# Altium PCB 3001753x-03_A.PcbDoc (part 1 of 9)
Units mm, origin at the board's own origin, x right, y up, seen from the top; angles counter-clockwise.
Board outline 210 x 130 mm, 8 copper layers (1-TOP, 2-GND, 3-INTOP, 4-PWR, 5-PWR, 6-INBOT, 7-GND, 8-BOTTOM), stack 1.646 mm thick; 676 components, 623 nets, 2861 pads, 2382 vias.
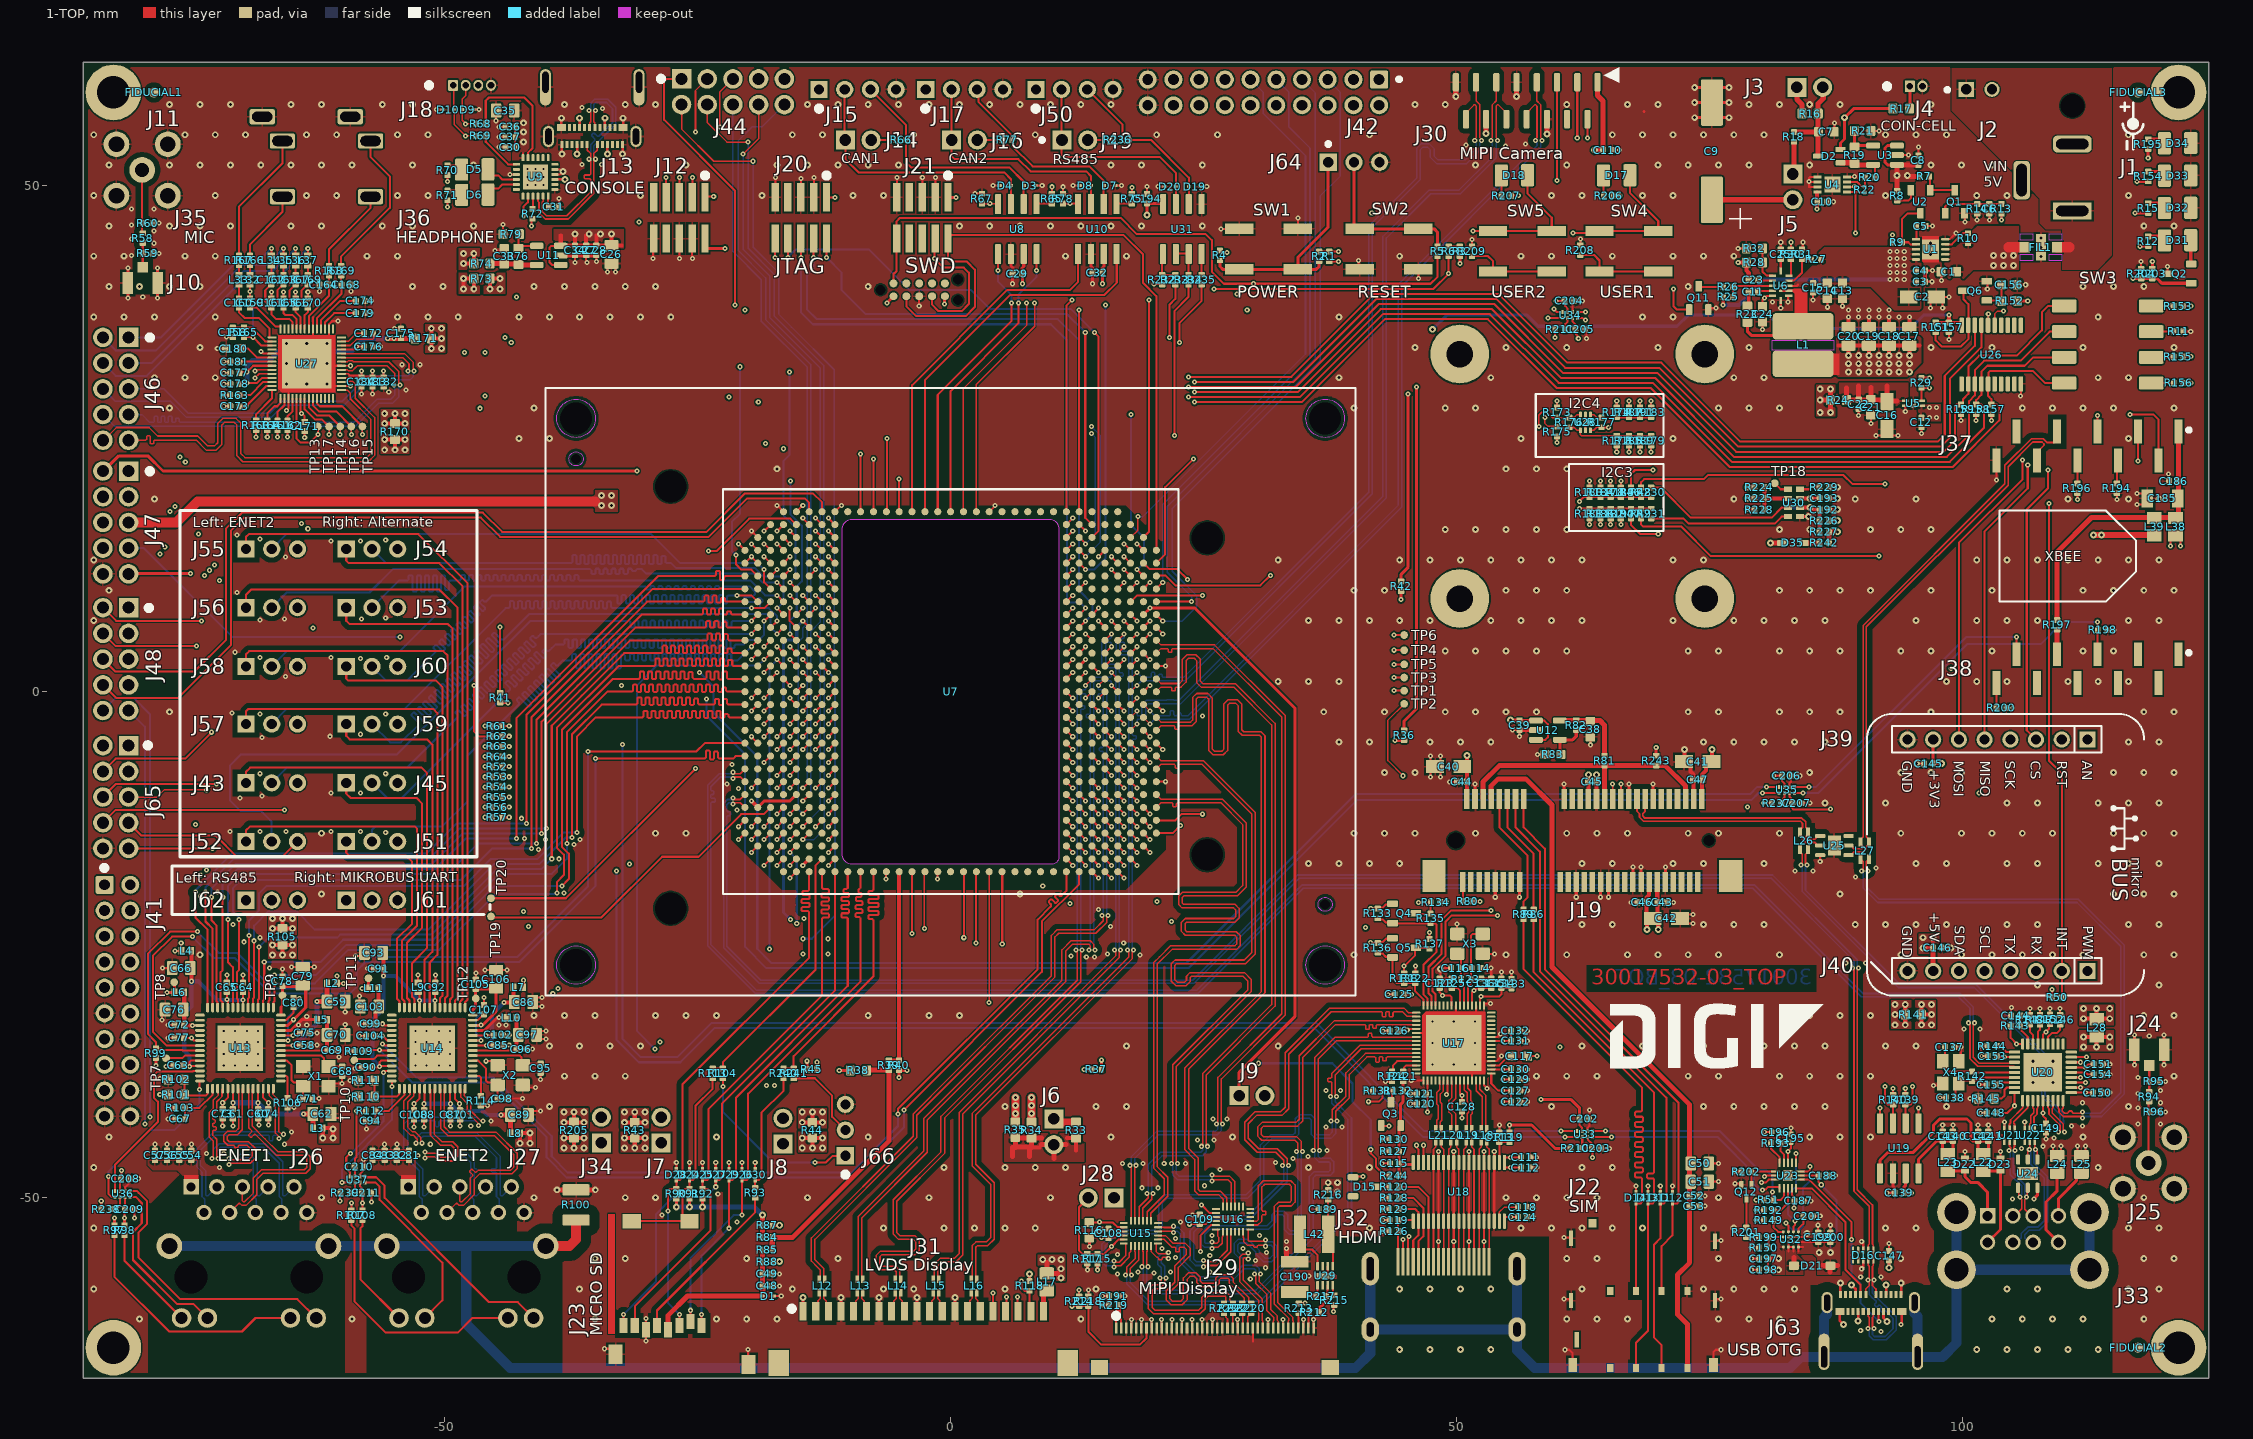
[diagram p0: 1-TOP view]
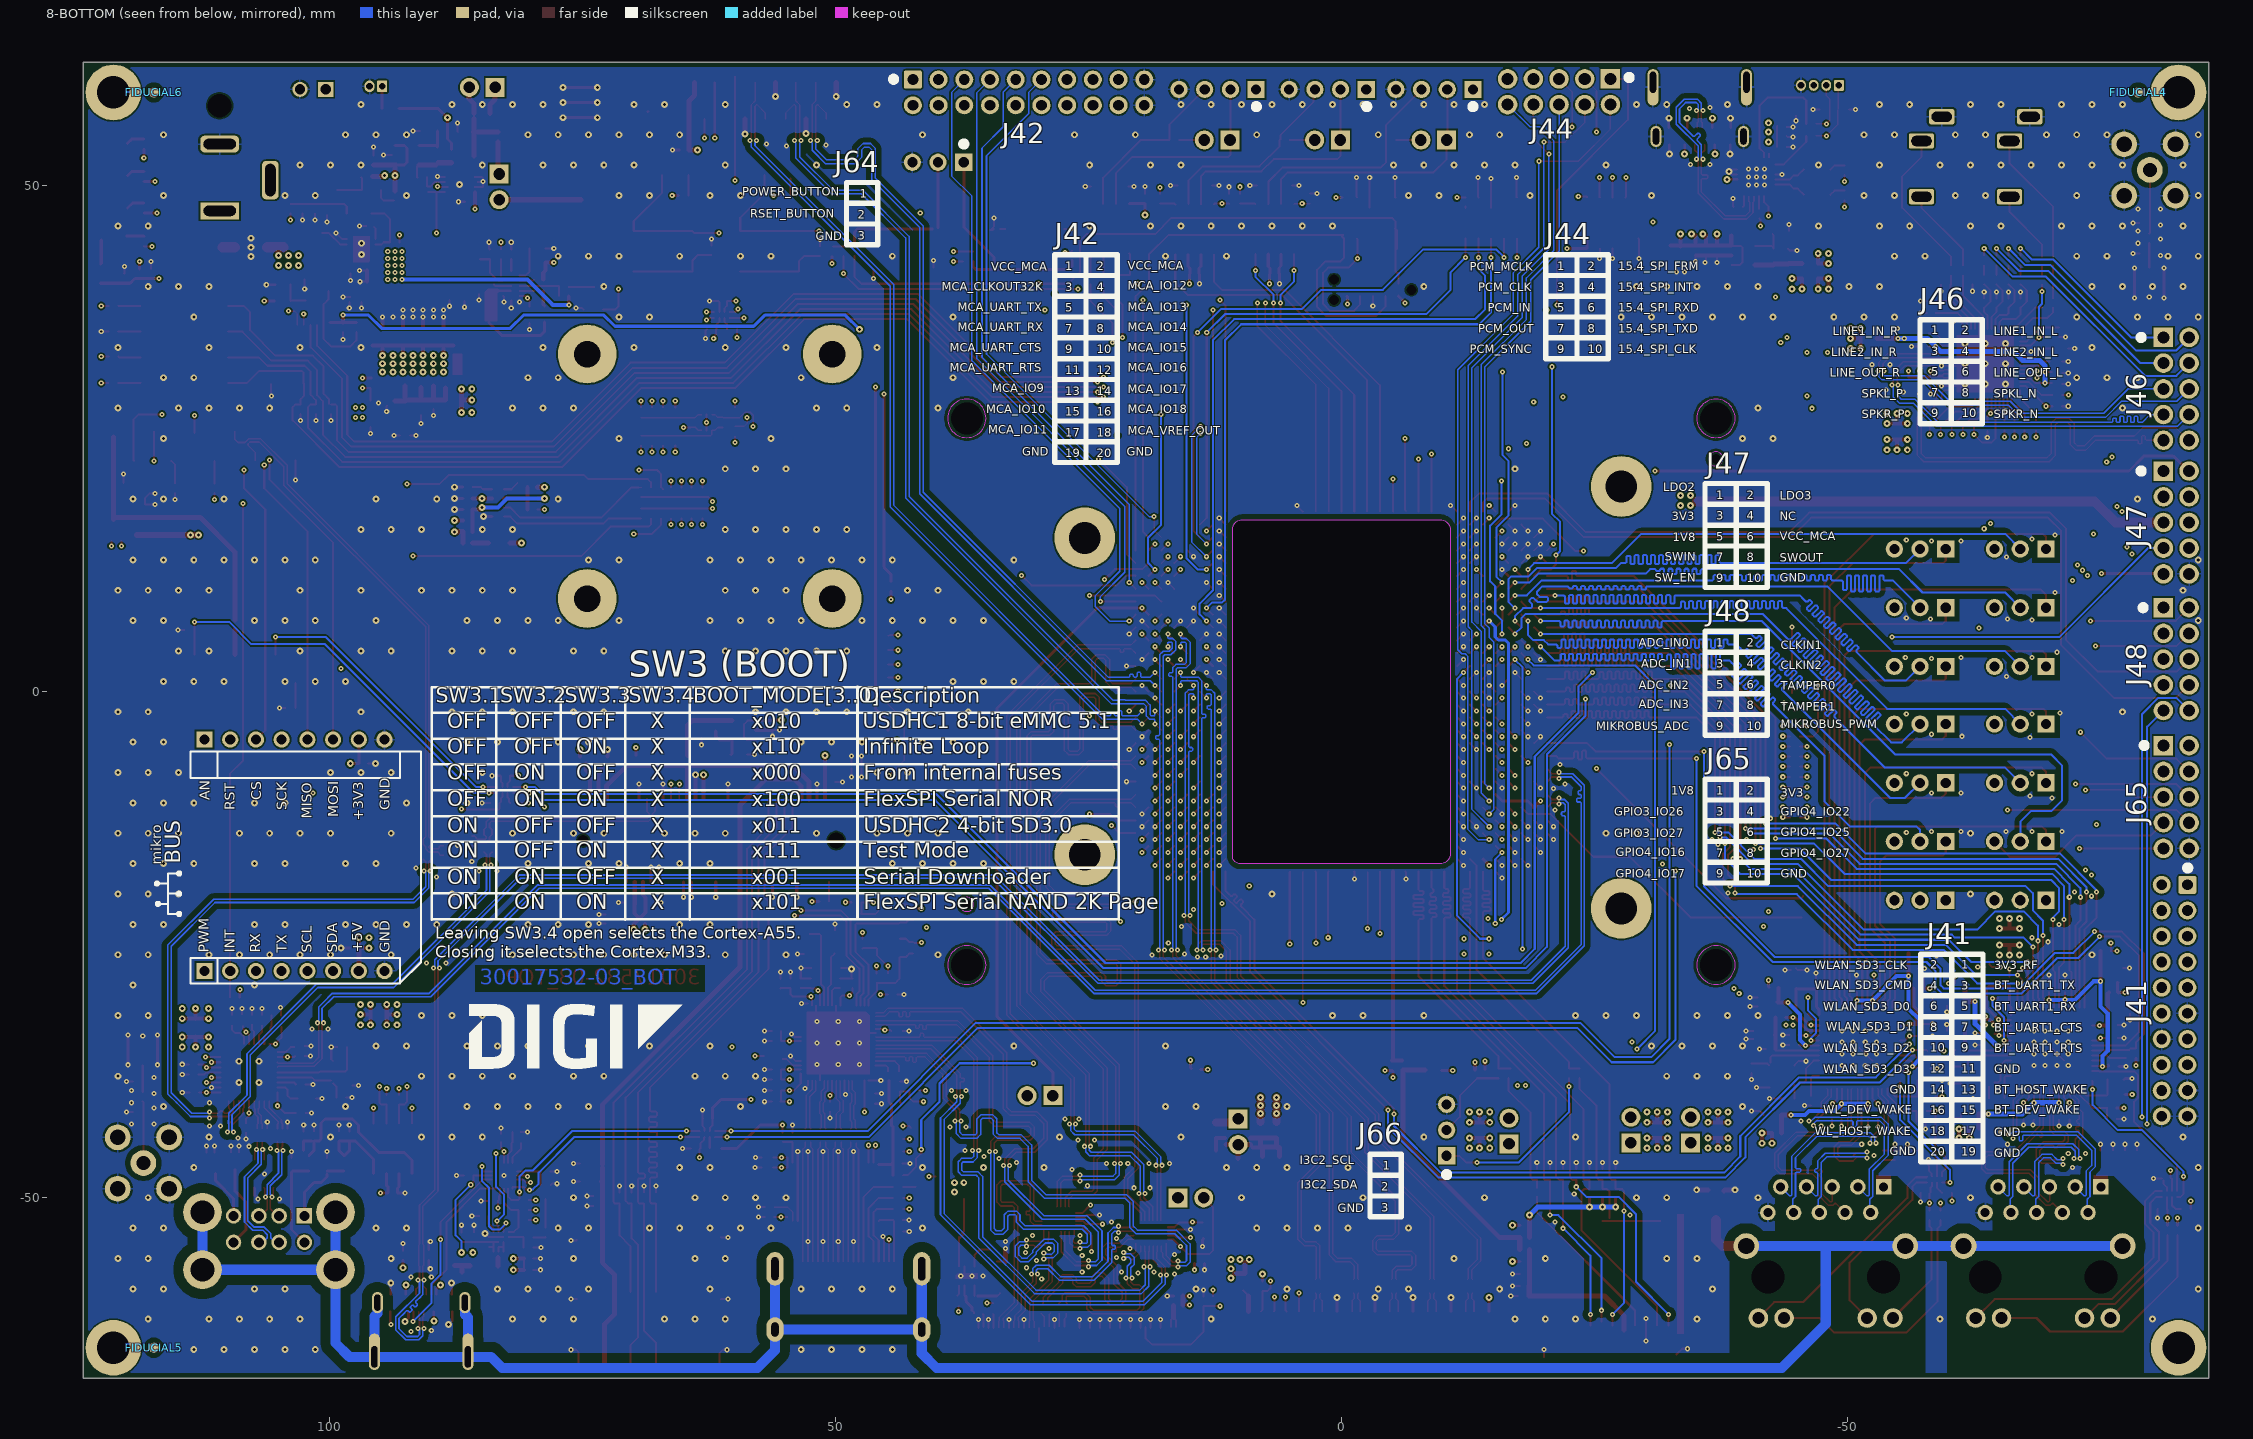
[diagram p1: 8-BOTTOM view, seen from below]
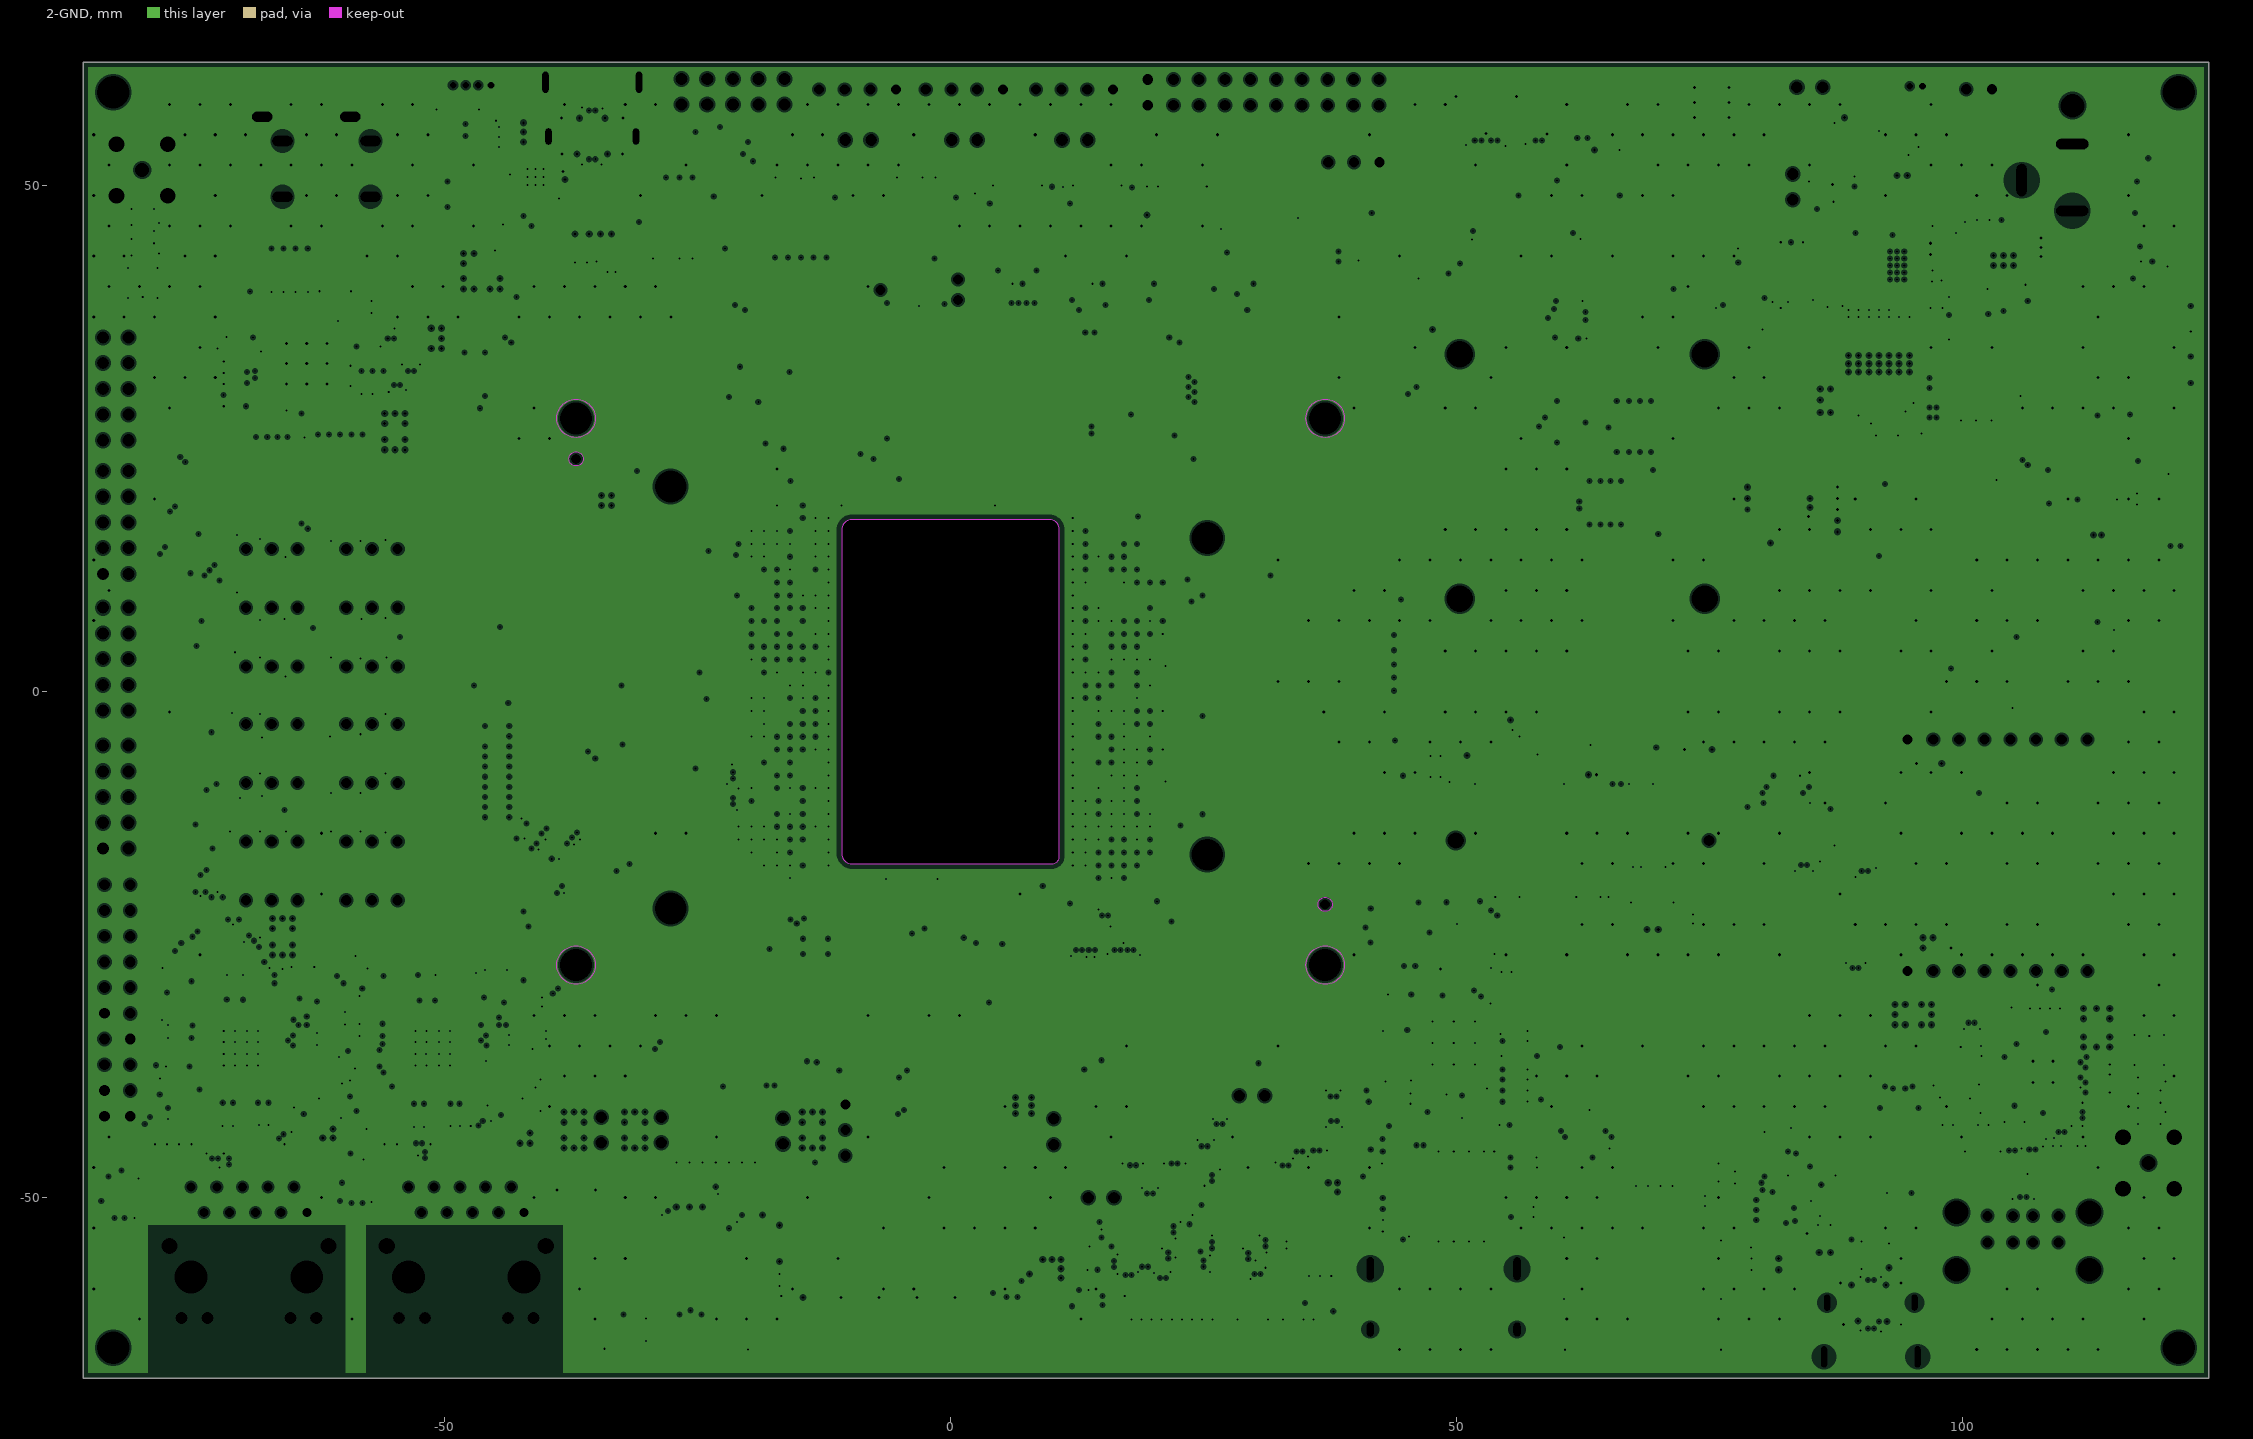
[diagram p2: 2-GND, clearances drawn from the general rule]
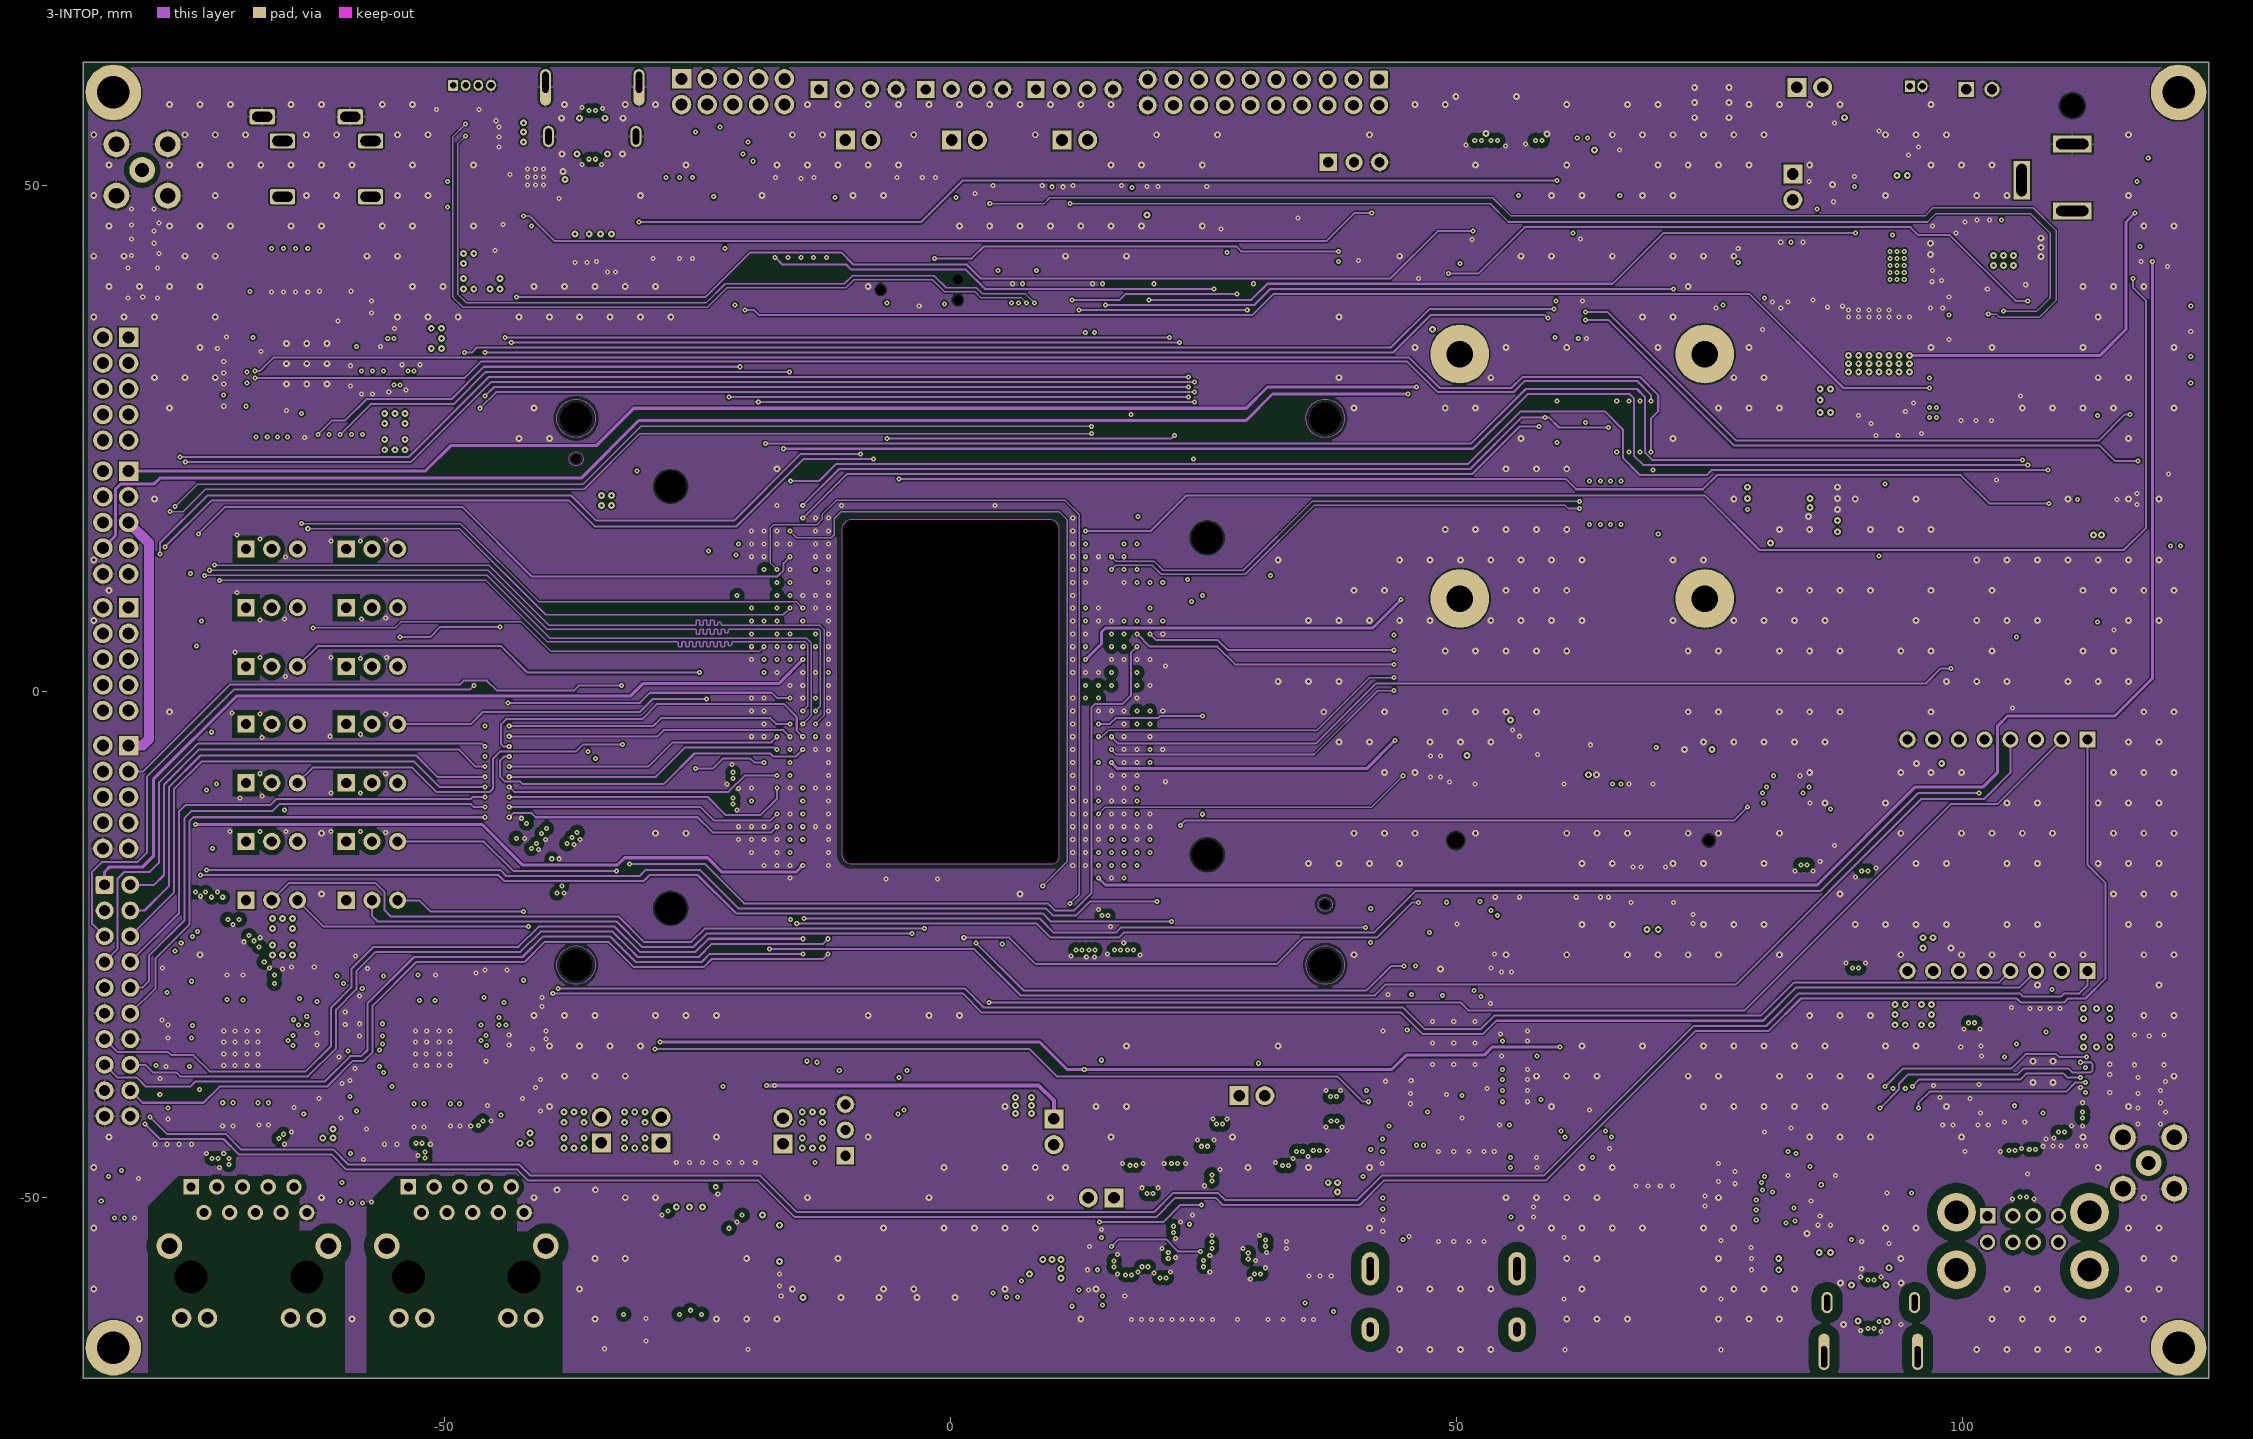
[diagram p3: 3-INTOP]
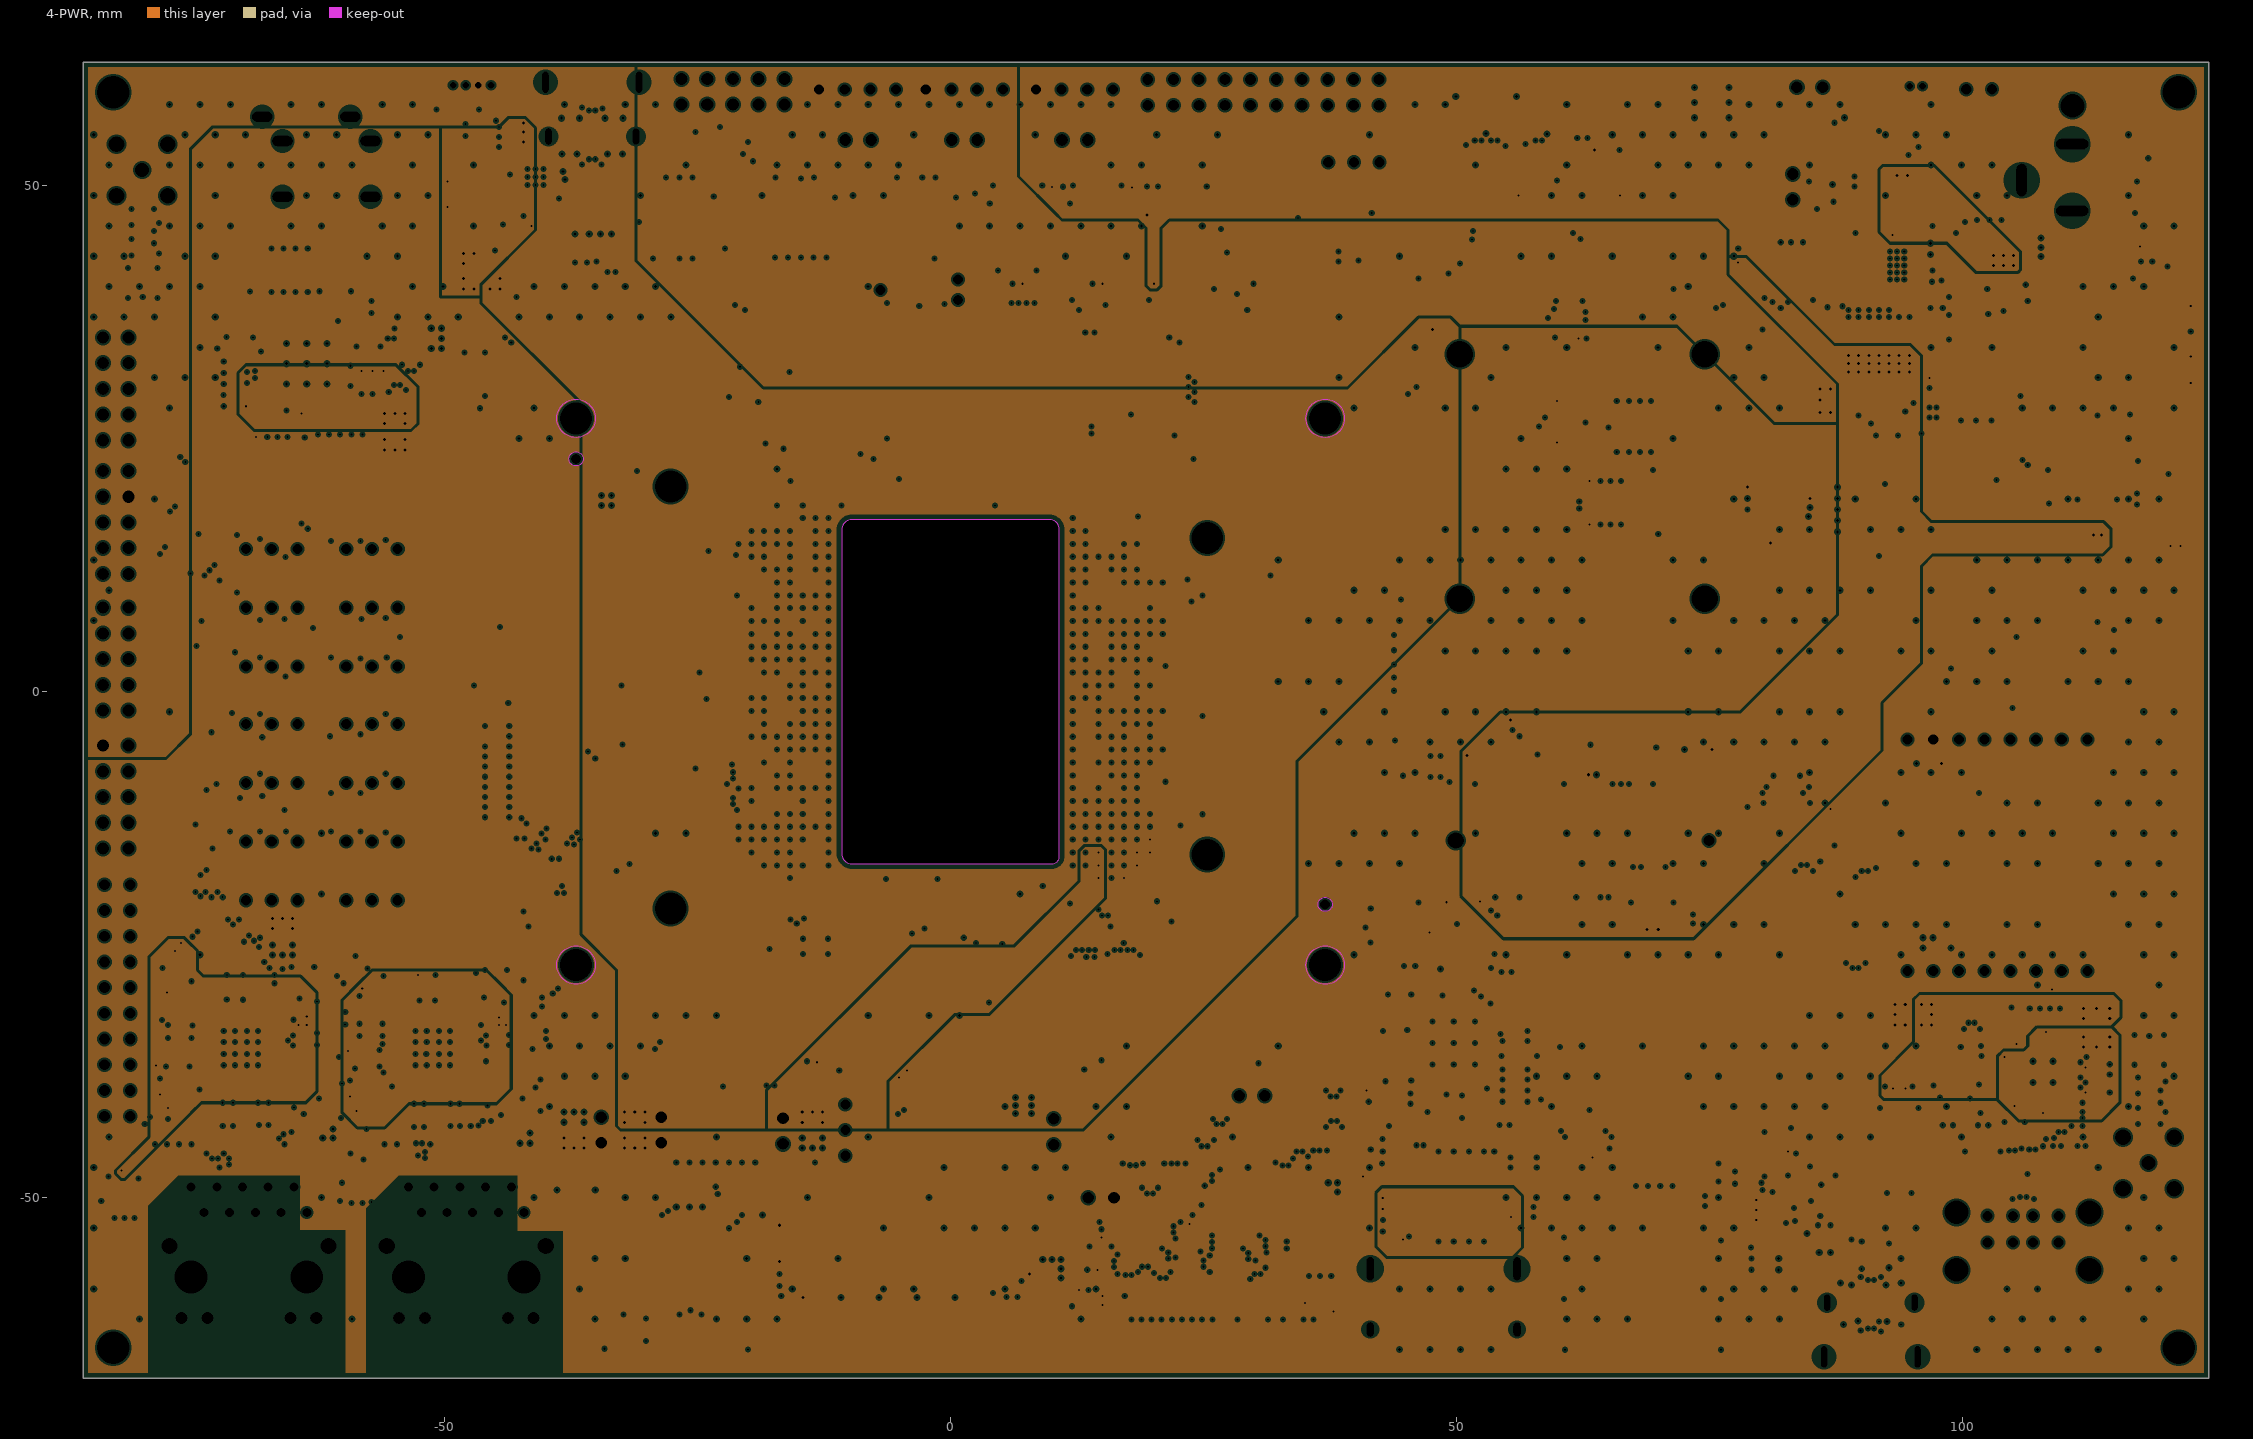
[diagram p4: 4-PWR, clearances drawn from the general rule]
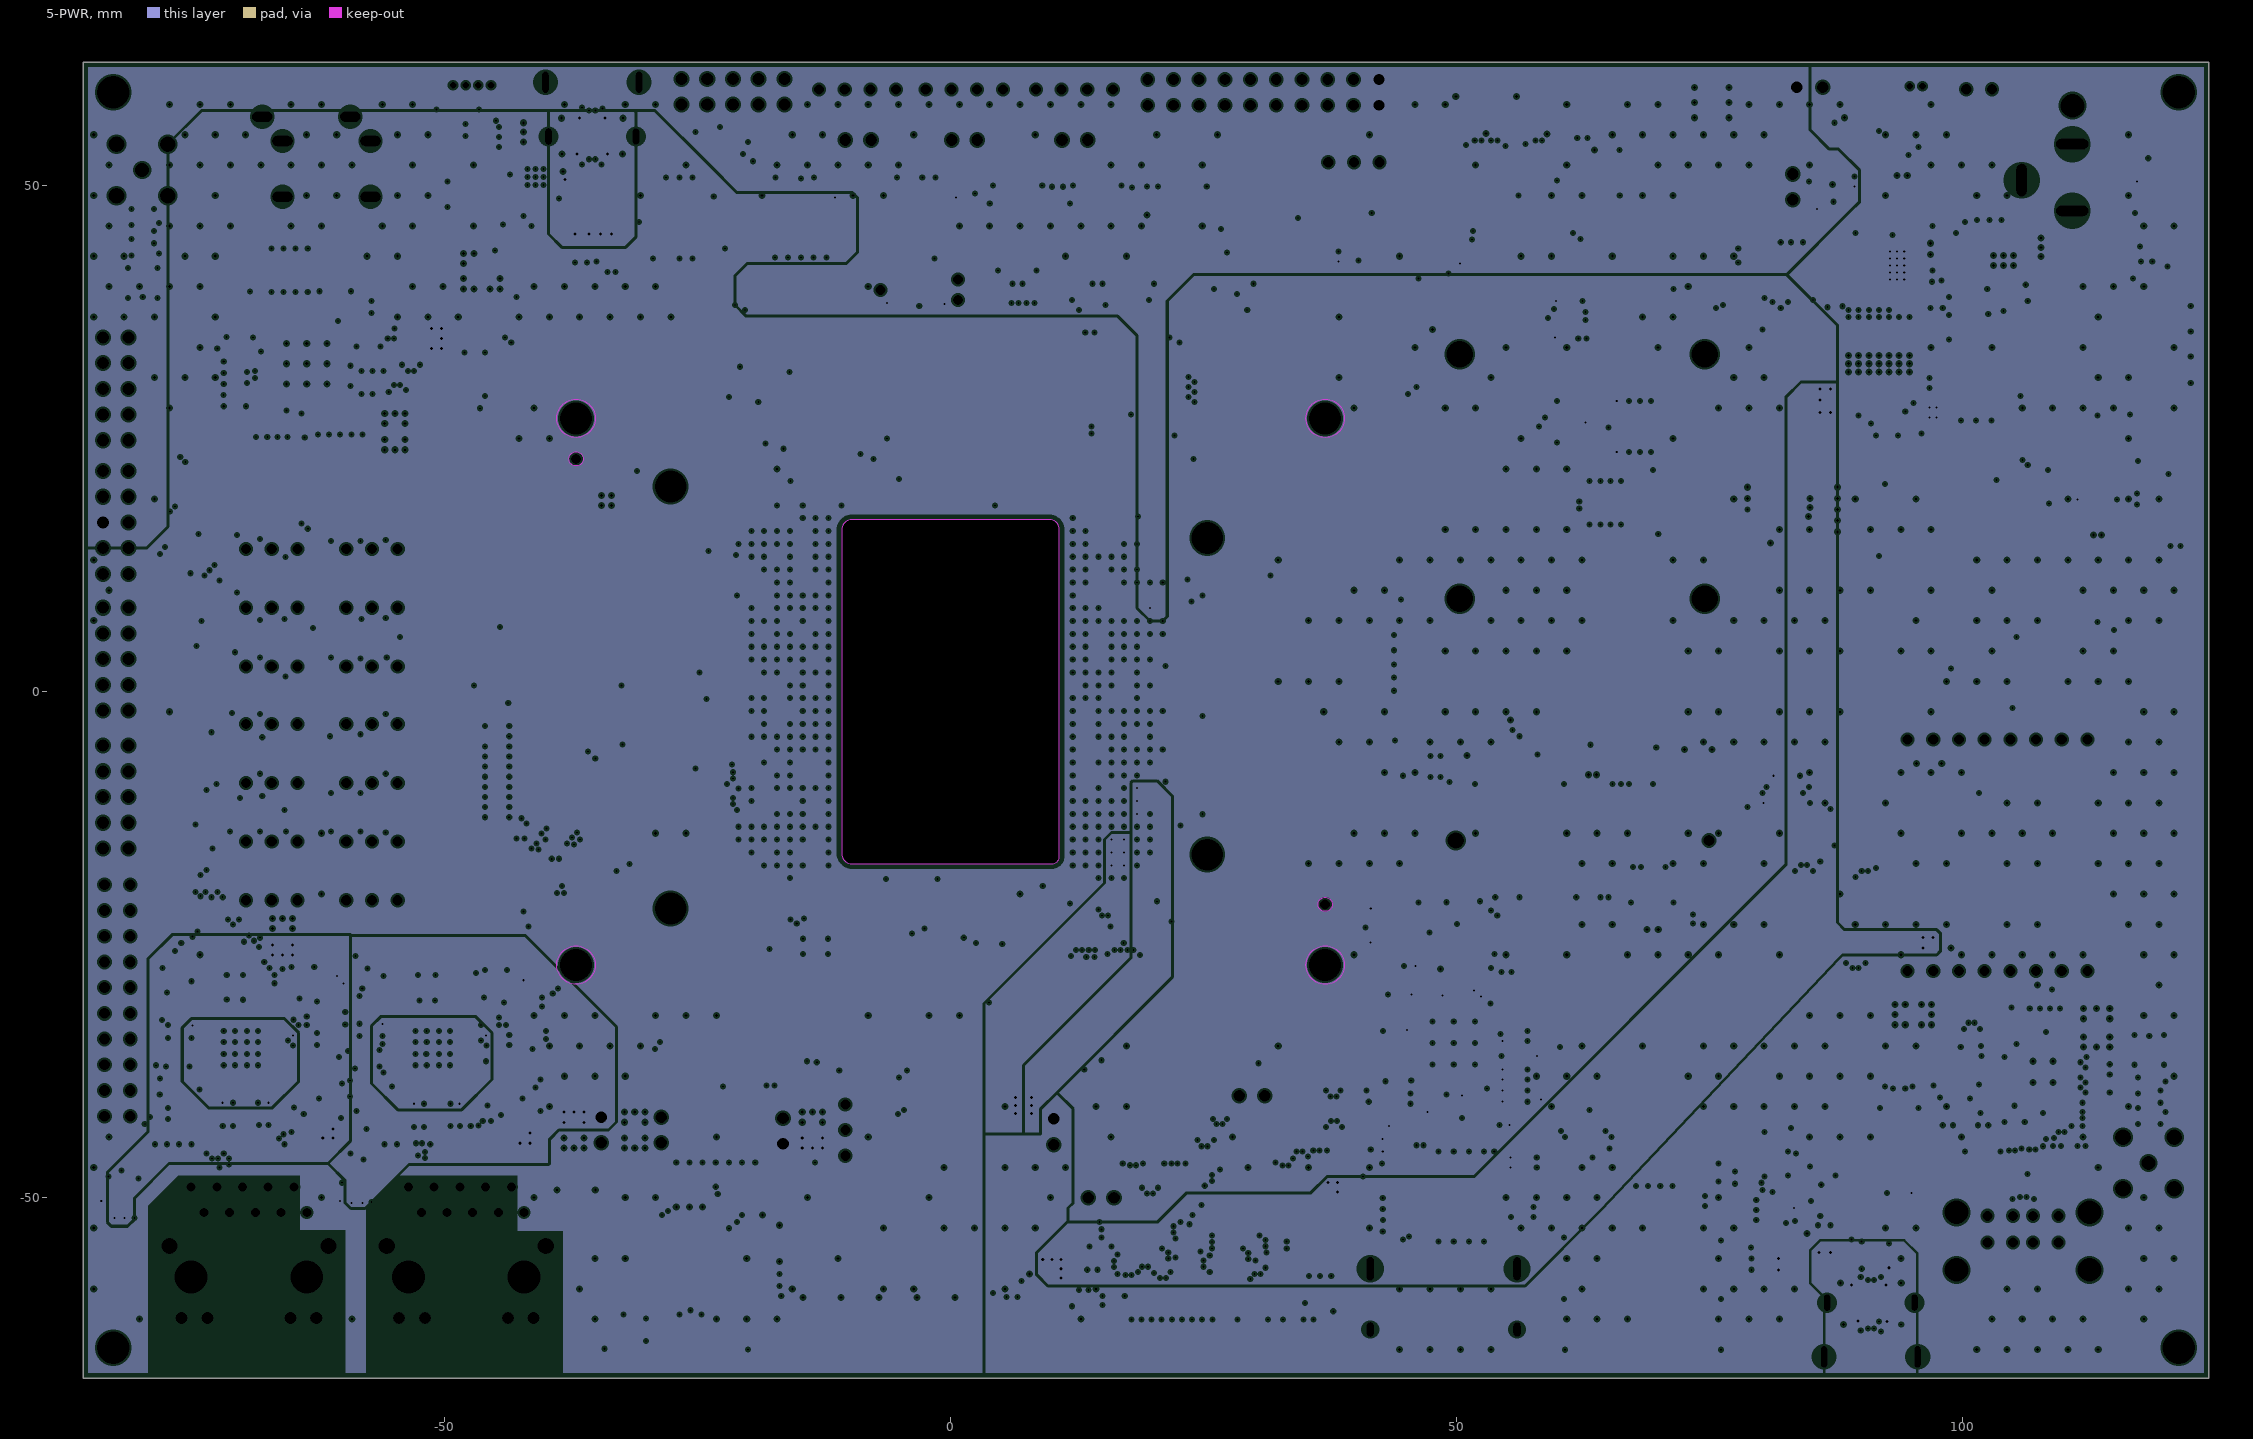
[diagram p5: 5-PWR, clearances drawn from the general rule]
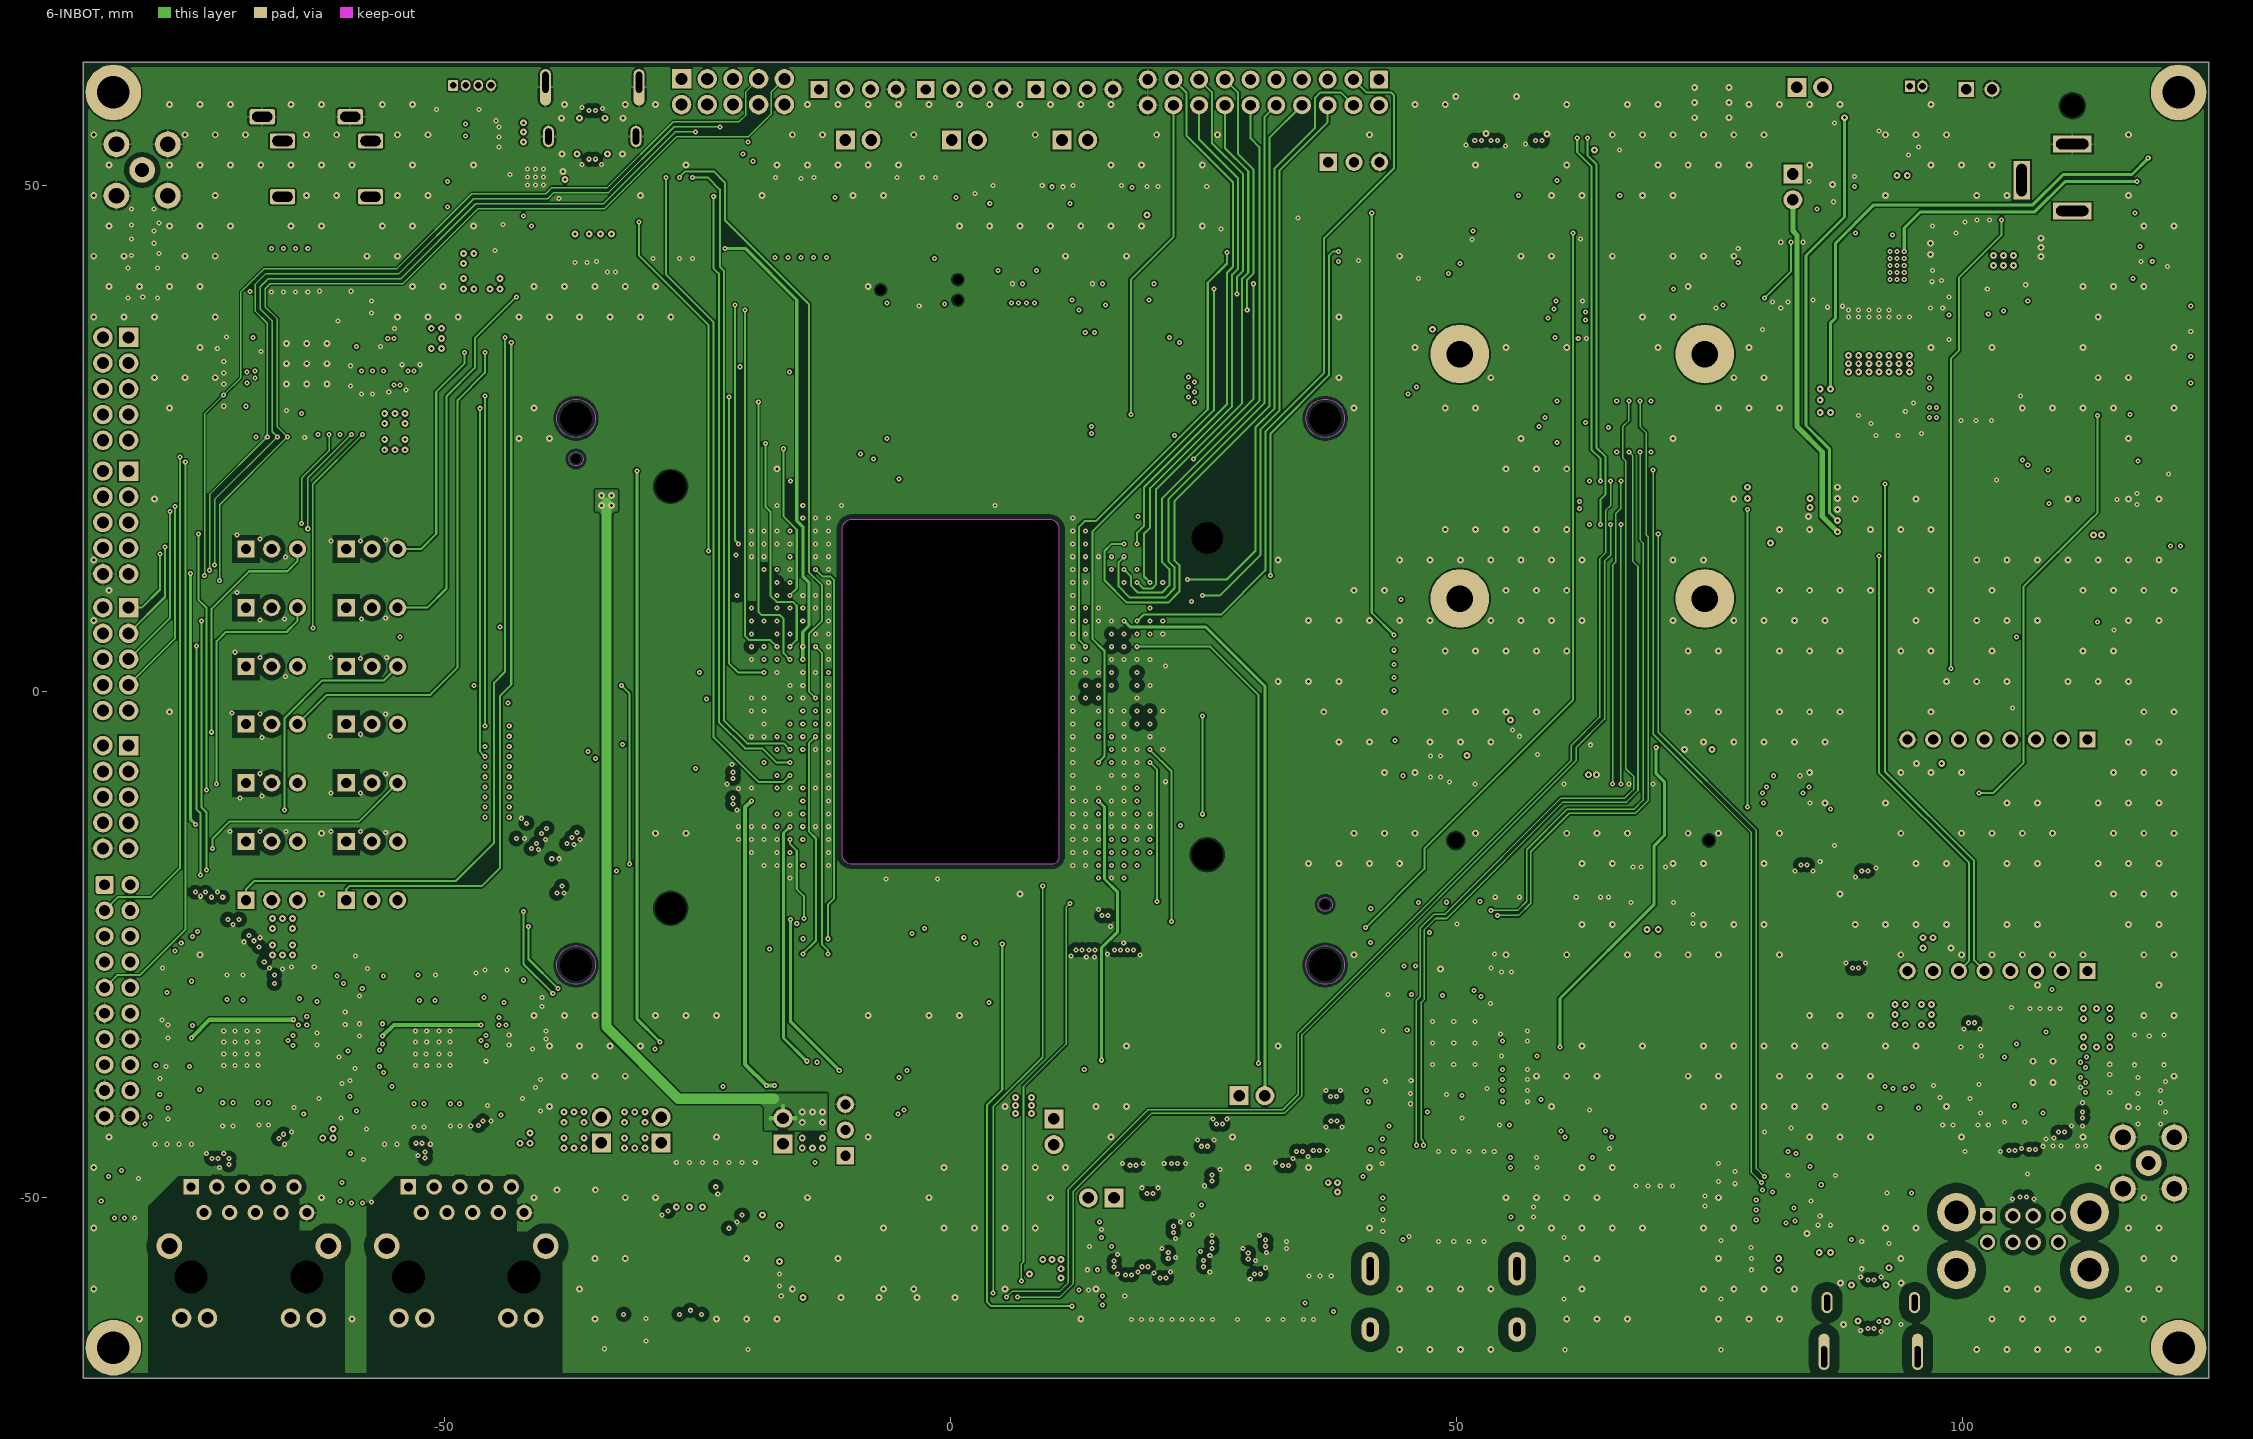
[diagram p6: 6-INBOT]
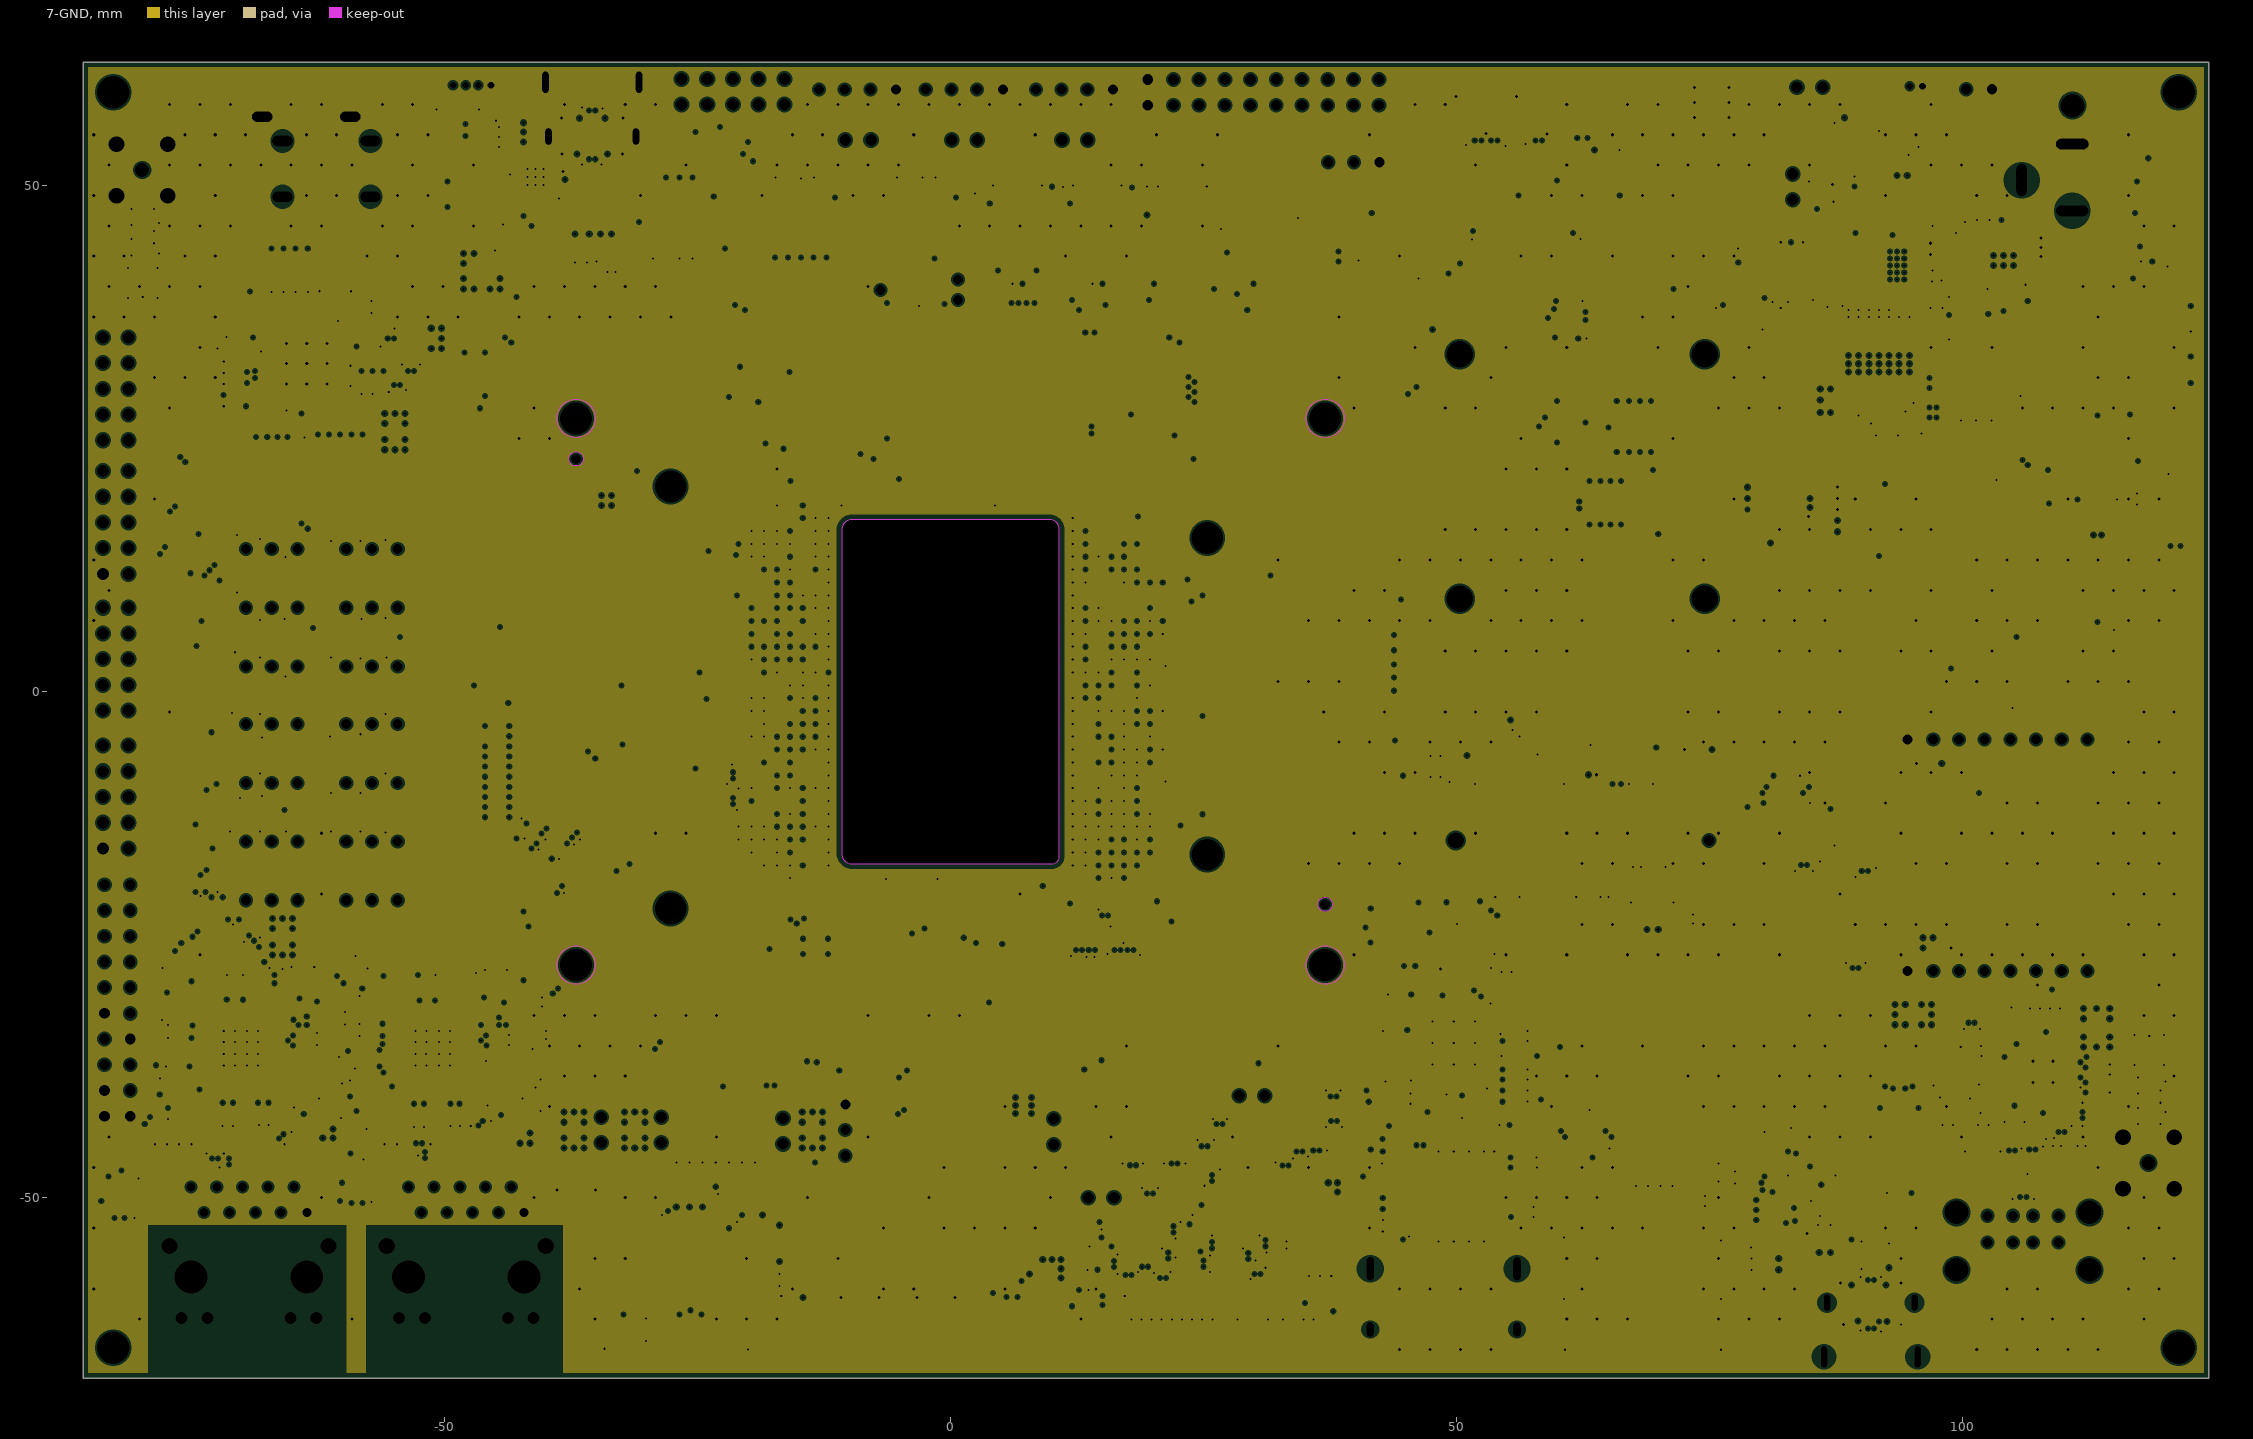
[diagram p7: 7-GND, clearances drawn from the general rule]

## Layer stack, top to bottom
Top Solder: solder mask 0.01, SM-003, Dk 4
1-TOP: signal copper 0.018
Dielectric1: prepreg 0.12, PP-017, Dk 4.2
2-GND: plane copper 0.035, net GND
Dielectric2: core 0.3, Core-015, Dk 4.2
3-INTOP: signal copper 0.035
Dielectric3: prepreg 0.18, PP-017, Dk 4.2
4-PWR: plane copper 0.035, net (Multiple Nets)
Dielectric6: core 0.2, Core-036, Dk 4.2
5-PWR: plane copper 0.035, net (Multiple Nets)
Dielectric10: prepreg 0.18, PP-017, Dk 4.2
6-INBOT: signal copper 0.035
Dielectric 12: core 0.3, Core-015, Dk 4.2
7-GND: plane copper 0.035, net GND
Dielectric11: prepreg 0.12, PP-017, Dk 4.2
8-BOTTOM: signal copper 0.018
Bottom Solder: solder mask 0.01, SM-003, Dk 4

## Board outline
-85.7,-67.8 -85.7,62.2 124.3,62.2 124.3,-67.8

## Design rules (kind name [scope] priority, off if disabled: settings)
AssemblyTestPointUsage [All] p1 off:
AssemblyTestpoint [All] p1 off: testpointundercomponent=TRUE minsize=1.016 maxsize=2.54 preferedsize=1.524 minholesize=0 maxholesize=1.016 preferedholesize=0.813 testpointgrid=0.025 usegrid=TRUE gridtolerance=0 allowsidetop=TRUE allowsidebottom=TRUE
BoardOutlineClearance [All - (OnLayer('Top Overlay') or OnLayer('Bottom Overlay') or OnLayer('Mechanical 13') or OnLayer('Mechanical 15'))] p1: gap=0.5 ignorepadtopadclearanceinfootprint=FALSE
Clearance Clearance_EDGE [OnLayer('Keep-Out Layer')] p1: gap=0.3 ignorepadtopadclearanceinfootprint=FALSE
Clearance Clearance_SHLD [InNet('SHLD')] p2: gap=1 ignorepadtopadclearanceinfootprint=FALSE
Clearance Clearance_Pair&50ohm [InDifferentialPairClass('DIFF85') or InDifferentialPairClass('DIFF90') or InDifferentialPairClass('DIFF100') or InNetClass('ANT') or InxSignalClass('SD2') or InxSignalClass('uSIM') or InxSignalClass('RGMII_ETH1') or InxSignalClass('RGMII_ETH2') vs InNamedPolygon('GND_PLANE')] p3: gap=0.5 ignorepadtopadclearanceinfootprint=FALSE
Clearance Clearance_Planes [All vs InNamedPolygon('GND_PLANE')] p4: gap=0.15 ignorepadtopadclearanceinfootprint=FALSE
Clearance [All] p5: gap=0.1 ignorepadtopadclearanceinfootprint=FALSE
ComponentClearance [All] p1: gap=0.2 collisioncheckmode=3 verticalgap=0.2 showdistances=FALSE
DiffPairsRouting DiffPairsRouting_100R_BGA [InDifferentialPairClass('DIFF100_BGA')] p1: maxlimit=0.14 minlimit=0.14 mostfreqgap=0.14 toplayer_minwidth=0.125 toplayer_maxwidth=0.125 toplayer_prefwidth=0.125 midlayer1_minwidth=0.125 midlayer1_maxwidth=0.125 midlayer1_prefwidth=0.125 midlayer2_minwidth=0.125 midlayer2_maxwidth=0.125 midlayer2_prefwidth=0.125 bottomlayer_minwidth=0.125 bottomlayer_maxwidth=0.125 bottomlayer_prefwidth=0.125 maxuncoupledlength=12.7
DiffPairsRouting DiffPairsRouting_100R [InDifferentialPairClass('DIFF100')] p2: maxlimit=0.204 minlimit=0.204 mostfreqgap=0.204 toplayer_minwidth=0.15 toplayer_maxwidth=0.15 toplayer_prefwidth=0.15 midlayer1_minwidth=0.15 midlayer1_maxwidth=0.15 midlayer1_prefwidth=0.15 midlayer2_minwidth=0.15 midlayer2_maxwidth=0.15 midlayer2_prefwidth=0.15 bottomlayer_minwidth=0.15 bottomlayer_maxwidth=0.15 bottomlayer_prefwidth=0.15 maxuncoupledlength=12.7
DiffPairsRouting DiffPairsRouting_90R [InDifferentialPairClass('DIFF90')] p3: maxlimit=0.15 minlimit=0.15 mostfreqgap=0.15 toplayer_minwidth=0.168 toplayer_maxwidth=0.168 toplayer_prefwidth=0.168 midlayer1_minwidth=0.168 midlayer1_maxwidth=0.168 midlayer1_prefwidth=0.168 midlayer2_minwidth=0.168 midlayer2_maxwidth=0.168 midlayer2_prefwidth=0.168 bottomlayer_minwidth=0.168 bottomlayer_maxwidth=0.168 bottomlayer_prefwidth=0.168 maxuncoupledlength=12.7
FabricationTestPointUsage [All] p1 off: valid=0 allowmultiple=FALSE
FabricationTestpoint [All] p1 off: side=3 testpointundercomponent=TRUE minsize=1.016 maxsize=2.54 preferedsize=1.524 minholesize=0 maxholesize=1.016 preferedholesize=0.813 testpointgrid=0.025 allowsidetop=TRUE allowsidebottom=TRUE usegrid=TRUE gridtolerance=0
Height [All] p1: minheight=0 maxheight=100 prefheight=20
HoleSize [All] p1: absolutevalues=TRUE maxlimit=10 minlimit=0.1 maxpercent=80.000 minpercent=20.000
MatchedLengths MatchedLengths_AUDIO [(InxSignal('SPKL_N_PP1') and InxSignal('SPKL_P_PP1')) or (InxSignal('SPKR_N_PP1') and InxSignal('SPKR_P_PP1'))] p1: tolerance=0.1 checknetsindiffpair=FALSE checkdiffpairvsdiffpair=TRUE checkxsignals=TRUE checkothers=TRUE
MatchedLengths MatchedLengths_DSI [InxSignalClass('DSI')] p2: tolerance=0.1 checknetsindiffpair=FALSE checkdiffpairvsdiffpair=TRUE checkxsignals=TRUE checkothers=TRUE
MatchedLengths MatchedLengths_CSI [InxSignalClass('DSI')] p3: tolerance=0.1 checknetsindiffpair=FALSE checkdiffpairvsdiffpair=TRUE checkxsignals=TRUE checkothers=TRUE
MatchedLengths MatchedLengths_USBHUB1 [InxSignalClass('USBH1')] p4: tolerance=0.1 checknetsindiffpair=FALSE checkdiffpairvsdiffpair=TRUE checkxsignals=TRUE checkothers=TRUE
MatchedLengths MatchedLengths_USBHUB2 [InxSignalClass('USBH2')] p5: tolerance=0.1 checknetsindiffpair=FALSE checkdiffpairvsdiffpair=TRUE checkxsignals=TRUE checkothers=TRUE
MatchedLengths MatchedLengths_ETH1 [InxSignalClass('ETH1')] p6: tolerance=0.1 checknetsindiffpair=FALSE checkdiffpairvsdiffpair=TRUE checkxsignals=TRUE checkothers=TRUE
MatchedLengths MatchedLengths_USB_HUB [InxSignalClass('USB_HUB')] p7: tolerance=0.1 checknetsindiffpair=FALSE checkdiffpairvsdiffpair=TRUE checkxsignals=TRUE checkothers=TRUE
MatchedLengths MatchedLengths_USB_OTG [(InxSignal('USB_OTG1_N_PP1') and InxSignal('USB_OTG1_P_PP1')) or (InxSignal('USB_OTG1_N_PP2') and InxSignal('USB_OTG1_P_PP2'))] p8: tolerance=0.1 checknetsindiffpair=FALSE checkdiffpairvsdiffpair=TRUE checkxsignals=TRUE checkothers=TRUE
MatchedLengths MatchedLengths_USB_CONSOLE [(InxSignal('CONSOLE_USB_N_PP1') and InxSignal('CONSOLE_USB_P_PP1')) or (InxSignal('CONSOLE_USB_N_PP2') and InxSignal('CONSOLE_USB_P_PP2'))] p9: tolerance=0.1 checknetsindiffpair=FALSE checkdiffpairvsdiffpair=TRUE checkxsignals=TRUE checkothers=TRUE
MatchedLengths MatchedLengths_ETH2 [InxSignalClass('ETH2')] p10: tolerance=0.1 checknetsindiffpair=FALSE checkdiffpairvsdiffpair=TRUE checkxsignals=TRUE checkothers=TRUE
MatchedLengths MatchedLengths_HDMI [InxSignalClass('HDMI')] p11: tolerance=0.1 checknetsindiffpair=FALSE checkdiffpairvsdiffpair=TRUE checkxsignals=TRUE checkothers=TRUE
MatchedLengths MatchedLengths_LT8912B [InxSignalClass('LT8912B')] p12: tolerance=0.1 checknetsindiffpair=FALSE checkdiffpairvsdiffpair=TRUE checkxsignals=TRUE checkothers=TRUE
MatchedLengths MatchedLengths_MIPI [InxSignalClass('MIPI_EXT')] p13: tolerance=0.1 checknetsindiffpair=FALSE checkdiffpairvsdiffpair=TRUE checkxsignals=TRUE checkothers=TRUE
MatchedLengths MatchedLengths_SD2 [InxSignalClass('SD2')] p14: tolerance=0.1 checknetsindiffpair=FALSE checkdiffpairvsdiffpair=TRUE checkxsignals=TRUE checkothers=TRUE
MatchedLengths MatchedLengths_PCM_Audio [InxSignalClass('PCM_Audio')] p15: tolerance=0.1 checknetsindiffpair=FALSE checkdiffpairvsdiffpair=TRUE checkxsignals=TRUE checkothers=TRUE
MatchedLengths MatchedLengths_LVDS [InxSignalClass('LVDS')] p16: tolerance=0.1 checknetsindiffpair=FALSE checkdiffpairvsdiffpair=TRUE checkxsignals=TRUE checkothers=TRUE
MatchedLengths MatchedLengths_RGMII_ETH [InxSignalClass('RGMII_ETH1')] p17: tolerance=0.1 checknetsindiffpair=FALSE checkdiffpairvsdiffpair=TRUE checkxsignals=TRUE checkothers=TRUE
MatchedLengths MatchedLengths_RGMII_ETH_MDIO [InxSignalClass('RGMII_ETH1_MDIO')] p18: tolerance=0.1 checknetsindiffpair=FALSE checkdiffpairvsdiffpair=TRUE checkxsignals=TRUE checkothers=TRUE
MatchedLengths MatchedLengths_uSIM [InxSignalClass('uSIM')] p19: tolerance=0.1 checknetsindiffpair=FALSE checkdiffpairvsdiffpair=TRUE checkxsignals=TRUE checkothers=TRUE
MatchedLengths MatchedLengths_USB_XBEE [InxSignalClass('USB_XBEE')] p20: tolerance=0.1 checknetsindiffpair=FALSE checkdiffpairvsdiffpair=TRUE checkxsignals=TRUE checkothers=TRUE
MatchedLengths MatchedLengths_USB_PCIe [InxSignalClass('USB_PCIe')] p21: tolerance=0.1 checknetsindiffpair=FALSE checkdiffpairvsdiffpair=TRUE checkxsignals=TRUE checkothers=TRUE
MatchedLengths MatchedLengths_RGMII_ETH2 [InxSignalClass('RGMII_ETH2')] p22: tolerance=0.1 checknetsindiffpair=FALSE checkdiffpairvsdiffpair=TRUE checkxsignals=TRUE checkothers=TRUE
MatchedLengths MatchedLengths_RGMII_ETH2_MDIO [InxSignalClass('RGMII_ETH2_MDIO')] p23: tolerance=0.1 checknetsindiffpair=FALSE checkdiffpairvsdiffpair=TRUE checkxsignals=TRUE checkothers=TRUE
MinimumSolderMaskSliver [All] p1: minsoldermaskwidth=0.1
PlaneClearance PlaneClearance_SHLD [InNet('SHLD')] p1: clearance=1
PlaneClearance PlaneClearance_ANT [InNetClass('ANT')] p2: clearance=0.5
PlaneClearance [All] p3: clearance=0.2
PlaneConnect PlaneConnect_VIA [IsVia] p1: planeconnectstyle=Direct reliefexpansion=0.15 reliefentries=4 reliefconductorwidth=0.2 reliefairgap=0.2
PlaneConnect [All] p2: planeconnectstyle=Relief reliefexpansion=0.15 reliefentries=4 reliefconductorwidth=0.2 reliefairgap=0.2
PolygonConnect PolygonConnect_VIA [IsVia] p1: connectstyle=Direct reliefconductorwidth=0.2 reliefentries=4 polygonreliefangle="90 Angle" airgapwidth=0.2
PolygonConnect [All] p2: connectstyle=Relief reliefconductorwidth=0.2 reliefentries=4 polygonreliefangle="90 Angle" airgapwidth=0.2
RoutingVias [All] p1: holewidth=0.2 width=0.5 viastyle="Through Hole" minholewidth=0.2 minwidth=0.4 maxholewidth=1 maxwidth=1
SilkToSilkClearance [All] p1 off: silktosilkclearance=0.254
SilkToSolderMaskClearance [IsPad] p1 off: minsilkscreentomaskgap=0.254 clearancetoexposedcopper=TRUE
SolderMaskExpansion [All] p1: expansion=0.05 istentingtop=FALSE
Width Width_ANT_COP [InNetClass('ANT_COP')] p1: maxlimit=0.5 minlimit=0.5 preferedwidth=0.5
Width Width_ANT [InNetClass('ANT')] p2: maxlimit=0.2 minlimit=0.2 preferedwidth=0.2
Width [All] p3: maxlimit=14 minlimit=0.125 preferedwidth=0.2 midlayer1_prefwidth=0.15 midlayer2_prefwidth=0.15 minimp=50.000000 maximp=50.000000 favimp=50.000000
17 further rules are at their usual default settings.

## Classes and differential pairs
component class "14 - USB Type C": C147 C187 C188 C195 C196 C197 C198 C199 C200 C201 D16 D21 J63 Q12 R51 R149 R150 R192 R193 R199 R201 R202 U23 U32
component class "06 - Shared interfaces lines selection": C202 C203 C204 C205 C206 C207 J43 J45 J51 J52 J53 J54 J55 J56 J57 J58 J59 J60 J61 J62 R210 R211 R237 U33 U34 U35
component class "13 - USB HUB": C137 C138 C139 C140 C141 C142 C143 C144 C148 C149 C150 C151 C152 C153 C154 C155 D22 D23 J33 L22 L23 L24 L25 L26 L27 L28 R139 R140 R141 R142 R143 R144 R145 R146 R147 R148 U19 U20 U21 U22 U24 U25 X4
component class "04 - CCIMX93 Digital interfaces": R104 R113 R240 R241 TP19 TP20
net class DIFF90: FAA_N FAA_P G_N G_P USB_HUB_N USB_HUB_P USB_OTG1_N USB_OTG1_P USB_PCIe_D_N USB_PCIe_D_P XBEE_USB_D_N XBEE_USB_D_P
component class "18 - Expansion connectors, LEDs and buttons": D17 D18 D31 D32 D33 D34 J41 J42 J44 J46 J47 J48 J65 J66 Q2 R12 R15 R154 R195 R203 R204 R206 R207 R208 R209 SW4 SW5
component class "08 - JTAG, SWD, uSD, Mini PCIe, uSIM": C38 C39 C40 C41 C42 C43 C44 C45 C46 C47 C48 C49 C50 C51 C52 C53 D1 D11 D12 D13 D14 D24 D25 D26 D27 D28 D29 D30 J19 J20 J21 J22 J23 J24 J25 R80 R81 R82 R83 R84 R85 R86 R87 R88 R89 R90 R91 R92 R93 R94 R95 R96 R243 SWD U12
component class "03 - CCIMX93 Power, Control, MCA": 3 J6 J7 J8 J9 R33 R34 R35 R36 R37 R38 R39 R40 R41 R42 R43 R44 R45 TP1 TP2 TP3 TP4 TP5 U7
net class DIFF100: ETH1_TXRXB_N ETH1_TXRXB_P ETH2_TXRXB_N ETH2_TXRXB_P HDMI_CLK_N HDMI_CLK_P HDMI_D0_N HDMI_D0_P HDMI_D1_N HDMI_D1_P HDMI_D2_N HDMI_D2_P L_CLK_N L_CLK_P L_D0_N L_D0_P L_D1_N L_D1_P L_D2_N L_D2_P L_D3_N L_D3_P LT8912B_CLK_N LT8912B_CLK_P LT8912B_D0_N LT8912B_D0_P LT8912B_D1_N LT8912B_D1_P LT8912B_D2_N LT8912B_D2_P LT8912B_D3_N LT8912B_D3_P LVDS_CLK_N LVDS_CLK_P LVDS_D0_N LVDS_D0_P LVDS_D1_N LVDS_D1_P LVDS_D2_N LVDS_D2_P LVDS_D3_N LVDS_D3_P MIPI_CSI1_CLK_N MIPI_CSI1_CLK_P MIPI_CSI1_DATA0_N MIPI_CSI1_DATA0_P MIPI_CSI1_DATA1_N MIPI_CSI1_DATA1_P MIPI_DSI1_CLK_N MIPI_DSI1_CLK_P MIPI_DSI1_DATA0_N MIPI_DSI1_DATA0_P MIPI_DSI1_DATA1_N MIPI_DSI1_DATA1_P MIPI_DSI1_DATA2_N MIPI_DSI1_DATA2_P MIPI_DSI1_DATA3_N MIPI_DSI1_DATA3_P MIPI_EXT_CLK_N MIPI_EXT_CLK_P MIPI_EXT_DATA0_N MIPI_EXT_DATA0_P MIPI_EXT_DATA1_N MIPI_EXT_DATA1_P MIPI_EXT_DATA2_N MIPI_EXT_DATA2_P MIPI_EXT_DATA3_N MIPI_EXT_DATA3_P
component class "09 - Gigabit Ethernet 1": C54 C55 C56 C57 C58 C59 C60 C61 C62 C63 C64 C65 C66 C67 C68 C69 C70 C71 C72 C73 C74 C75 C76 C77 C78 C79 C80 C208 C209 J26 L2 L3 L4 L5 L6 R97 R98 R99 R100 R101 R102 R103 R105 R106 R238 TP7 TP8 TP9 U13 U36 X1
differential pair class DIFF100: ETH1_TXRXA ETH1_TXRXB ETH1_TXRXC ETH1_TXRXD ETH2_TXRXA ETH2_TXRXB ETH2_TXRXC ETH2_TXRXD HDMI_CLK HDMI_D0 HDMI_D1 HDMI_D2 L_CLK L_D0 L_D1 L_D2 L_D3 LT8912B_CLK LT8912B_D0 LT8912B_D1 LT8912B_D2 LT8912B_D3 LVDS_CLK LVDS_D0 LVDS_D1 LVDS_D2 LVDS_D3 MIPI_CSI1_CLK MIPI_CSI1_DATA0 MIPI_CSI1_DATA1 MIPI_DSI1_CLK MIPI_DSI1_DATA0 MIPI_DSI1_DATA1 MIPI_DSI1_DATA2 MIPI_DSI1_DATA3 MIPI_EXT_CLK MIPI_EXT_DATA0 MIPI_EXT_DATA1 MIPI_EXT_DATA2 MIPI_EXT_DATA3
differential pair class DIFF90: B C CONSOLE_USB FAA G U1 U2 USB_HUB USB_OTG1 USB_PCIe_D USBH1_D USBH2_D XBEE_USB_D
component class "20 - History, Mechanicals": FIDUCIAL1 FIDUCIAL2 FIDUCIAL3 FIDUCIAL4 FIDUCIAL5 FIDUCIAL6 LBL1 TXT1
component class "17 - I2C, XBee, MIKROBUS": C145 C146 C185 C186 J37 J38 J39 J40 L38 L39 R46 R47 R48 R49 R50 R172 R173 R174 R175 R176 R177 R178 R179 R180 R181 R182 R183 R184 R185 R186 R187 R188 R189 R190 R191 R194 R196 R197 R198 R200 R230 R231 U28
component class "11 - MIPI switch and display, MIPI camera, LVDS": C108 C109 C110 C189 C190 C191 J28 J29 J30 J31 L12 L13 L14 L15 L16 L17 L42 R115 R116 R117 R118 R212 R213 R214 R215 R216 R217 R218 R219 R220 R221 R222 R223 U15 U16 U29
component class "16 - Audio": C158 C159 C160 C161 C162 C163 C164 C165 C166 C167 C168 C169 C170 C171 C172 C173 C174 C175 C176 C177 C178 C179 C180 C181 C182 C183 C184 J35 J36 L32 L33 L34 L35 L36 L37 m R160 R161 R162 R163 R164 R165 R166 R167 R168 R169 R170 R171 TP13 TP14 TP15 TP16 TP17 U27
component class "15 - Bootstrap": C156 C157 Q6 R11 R151 R152 R153 R155 R156 R157 R158 R159 SW3 U26
component class "10 - Gigabit Ethernet 2": C81 C82 C83 C84 C85 C86 C87 C88 C89 C90 C91 C92 C93 C94 C95 C96 C97 C98 C99 C100 C101 C102 C103 C104 C105 C106 C107 C210 C211 J27 J34 L7 L8 L9 L10 L11 R107 R108 R109 R110 R111 R112 R114 R205 R239 TP10 TP11 TP12 U14 U37 X2
component class "12 - MIPI to HDMI bridge": C111 C112 C113 C114 C115 C116 C117 C118 C119 C120 C121 C122 C123 C124 C125 C126 C127 C128 C129 C130 C131 C132 C133 C134 C135 C136 D15 J32 L18 L19 L20 L21 Q3 Q4 Q5 R119 R120 R121 R122 R123 R124 R125 R126 R127 R128 R129 R130 R131 R132 R133 R134 R135 R136 R137 R138 R244 U17 U18 X3
component class "07 - Console, CAN, RS485, RTC": C26 C27 C28 C29 C30 C31 C32 C33 C34 C35 C36 C37 C192 C193 C194 D3 D4 D5 D6 D7 D8 D9 D10 D19 D20 J13 J14 J15 J16 J17 J18 J49 J50 R65 R66 R67 R68 R69 R70 R71 R72 R73 R74 R75 R76 R77 R78 R79 R224 R225 R226 R227 R228 R229 R232 R233 R234 R235 R236 TP6 TP18 U8 U9 U10 U11 U30 U31
component class "05 - CCIMX93 RF": J10 J11 J12 R52 R53 R54 R55 R56 R57 R58 R59 R60 R61 R62 R63 R64
component class "02 - Power, reset": C1 C2 C3 C4 C5 C6 C7 C8 C9 C10 C11 C12 C13 C14 C15 C16 C17 C18 C19 C20 C21 C22 C23 C24 C25 D2 D35 FIL1 J1 J2 J3 J4 J5 J64 L1 Q1 Q11 R1 R2 R3 R4 R5 R6 R7 R8 R9 R10 R13 R14 R16 R17 R18 R19 R20 R21 R22 R23 R24 R25 R26 R27 R28 R29 R30 R31 R32 R242 SW1 SW2 U1 U2 U3 U4 U5 U6
net class ANT: NetJ10_1 NetJ11_1 NetJ24_1 NetJ25_1
net class 0.2A: NetD2_1 NetD4_2 NetD4_3 VCC_RTC
net class 5A: NetFIL1_1 VIN VIN_PROT
differential pair XBEE_USB_D: +XBEE_USB_D_P -XBEE_USB_D_N
differential pair USB_OTG1: +USB_OTG1_P -USB_OTG1_N
differential pair L_D3: +L_D3_P -L_D3_N
differential pair L_D2: +L_D2_P -L_D2_N
differential pair L_D1: +L_D1_P -L_D1_N
differential pair L_D0: +L_D0_P -L_D0_N
differential pair L_CLK: +L_CLK_P -L_CLK_N
differential pair U2: +U2_P -U2_N
differential pair U1: +U1_P -U1_N
differential pair USB_PCIe_D: +USB_PCIe_D_P -USB_PCIe_D_N
differential pair USB_HUB: +USB_HUB_P -USB_HUB_N
differential pair MIPI_EXT_DATA3: +MIPI_EXT_DATA3_P -MIPI_EXT_DATA3_N
differential pair MIPI_EXT_DATA2: +MIPI_EXT_DATA2_P -MIPI_EXT_DATA2_N
differential pair MIPI_EXT_DATA1: +MIPI_EXT_DATA1_P -MIPI_EXT_DATA1_N
differential pair MIPI_EXT_DATA0: +MIPI_EXT_DATA0_P -MIPI_EXT_DATA0_N
differential pair MIPI_EXT_CLK: +MIPI_EXT_CLK_P -MIPI_EXT_CLK_N
differential pair MIPI_DSI1_DATA3: +MIPI_DSI1_DATA3_P -MIPI_DSI1_DATA3_N
differential pair MIPI_DSI1_DATA2: +MIPI_DSI1_DATA2_P -MIPI_DSI1_DATA2_N
differential pair MIPI_DSI1_DATA1: +MIPI_DSI1_DATA1_P -MIPI_DSI1_DATA1_N
differential pair MIPI_DSI1_DATA0: +MIPI_DSI1_DATA0_P -MIPI_DSI1_DATA0_N
differential pair MIPI_DSI1_CLK: +MIPI_DSI1_CLK_P -MIPI_DSI1_CLK_N
differential pair MIPI_CSI1_DATA1: +MIPI_CSI1_DATA1_P -MIPI_CSI1_DATA1_N
differential pair MIPI_CSI1_DATA0: +MIPI_CSI1_DATA0_P -MIPI_CSI1_DATA0_N
differential pair MIPI_CSI1_CLK: +MIPI_CSI1_CLK_P -MIPI_CSI1_CLK_N
differential pair LVDS_D3: +LVDS_D3_P -LVDS_D3_N
differential pair LVDS_D2: +LVDS_D2_P -LVDS_D2_N
differential pair LVDS_D1: +LVDS_D1_P -LVDS_D1_N
differential pair LVDS_D0: +LVDS_D0_P -LVDS_D0_N
differential pair LVDS_CLK: +LVDS_CLK_P -LVDS_CLK_N
differential pair LT8912B_D3: +LT8912B_D3_P -LT8912B_D3_N
differential pair LT8912B_D2: +LT8912B_D2_P -LT8912B_D2_N
differential pair LT8912B_D1: +LT8912B_D1_P -LT8912B_D1_N
differential pair LT8912B_D0: +LT8912B_D0_P -LT8912B_D0_N
differential pair LT8912B_CLK: +LT8912B_CLK_P -LT8912B_CLK_N
differential pair G: +G_P -G_N
differential pair FAA: +FAA_P -FAA_N
differential pair ETH2_TXRXD: +ETH2_TXRXD_P -ETH2_TXRXD_N
differential pair ETH2_TXRXC: +ETH2_TXRXC_P -ETH2_TXRXC_N
differential pair ETH2_TXRXB: +ETH2_TXRXB_P -ETH2_TXRXB_N
differential pair ETH2_TXRXA: +ETH2_TXRXA_P -ETH2_TXRXA_N
differential pair ETH1_TXRXD: +ETH1_TXRXD_P -ETH1_TXRXD_N
differential pair ETH1_TXRXC: +ETH1_TXRXC_P -ETH1_TXRXC_N
differential pair ETH1_TXRXB: +ETH1_TXRXB_P -ETH1_TXRXB_N
differential pair ETH1_TXRXA: +ETH1_TXRXA_P -ETH1_TXRXA_N
differential pair CONSOLE_USB: +CONSOLE_USB_P -CONSOLE_USB_N
differential pair HDMI_D2: +HDMI_D2_P -HDMI_D2_N
differential pair HDMI_D1: +HDMI_D1_P -HDMI_D1_N
differential pair HDMI_D0: +HDMI_D0_P -HDMI_D0_N
differential pair HDMI_CLK: +HDMI_CLK_P -HDMI_CLK_N
differential pair SPKR: +SPKR_P -SPKR_N
differential pair SPKL: +SPKL_P -SPKL_N
differential pair USBH1_D: +USBH1_D_P -USBH1_D_N
differential pair USBH2_D: +USBH2_D_P -USBH2_D_N
differential pair MIC: +MIC_P -MIC_N

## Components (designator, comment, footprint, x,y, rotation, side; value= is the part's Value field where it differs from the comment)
C1 "22µF" CAPC1608X90N 98.6,41.5 r0 top
C2 "100uF" CAPMP3216X120N 96,39 r0 top
C3 "10uF" CAPC1005X55N#1 95.8,40.5 r180 top
C4 "1.0uF" CAPC1005X55N#1 95.8,41.6 r180 top
C5 "47pF" CAPC1005X55N#2 95.84,46 r180 top
C6 "100nF" CAPC1005X55N#2 102.6,47.7 r270 top
C7 "2.2UF" CAPC1608X90N 86.5,55.3 r180 top
C8 "1.0uF" CAPC1005X55N#2 95.6,52.5 r270 top
C9 "NEXC474Z3.5V10.5X8.5TRF" NEXC474Z3.5V10.5X8.5TRF 75.2,53.4 r180 top
C10 "1.0uF" CAPC1005X55N#1 86.1,48.4 r0 top
C11 "100nF" CAPC1005X55N#2 79.3,39.5 r180 top
C12 "10uF" CAPC1005X55N#1 95.9,26.6 r90 top
C13 "22µF" CAPC1608X90N 88.1,39.6 r90 top
C14 "22µF" CAPC1608X90N 86.6,39.6 r90 top
C15 "100nF" CAPC1005X55N#2 85.2,39.9 r90 top
C16 "100uF" CAPMP3216X120N 92.5,27.3 r270 top
C17 "10uF" CAPC2013X135N#1 94.7,35.1 r270 top
C18 "10uF" CAPC2013X135N#1 92.7,35.1 r270 top
C19 "10uF" CAPC2013X135N#1 90.7,35.1 r270 top
C20 "10uF" CAPC2013X135N#1 88.7,35.1 r270 top
C21 "22µF" CAPC1608X90N 90.9,28.1 r90 top
C22 "100nF" CAPC1005X55N#1 89.7,28.4 r90 top
C23 "47pF" CAPC1005X55N#2 79.3,40.7 r180 top
C24 "2.2UF" CAPC1608X90N 80.2,37.3 r90 top
C25 "15nF" CAPC1005X55N#2 82,43.2 r270 top
C26 "10uF" CAPC2013X135N#1 -33.5,43.2 r90 top
C27 "100nF" CAPC1005X55N#2 -36,43.6 r90 top
C28 "100nF" CAPC1005X55N#2 -35,43.6 r90 top
C29 "100nF" CAPC1005X55N#2 6.6,41.3 r180 top
C30 "100nF" CAPC1005X55N#1 -43.5,53.8 r0 top
C31 "1.0uF" CAPC1005X55N#1 -39.2,47.9 r0 top
C32 "100nF" CAPC1005X55N#1 14.5,41.4 r180 top
C33 "2.2UF" CAPC1608X90N -44.1,43 r270 top
C34 "1.0uF" CAPC1005X55N#1 -37.1,43.6 r270 top
C35 "10uF" CAPC2013X135N#1 -44,57.4 r0 top
C36 "100nF" CAPC1005X55N#1 -43.5,55.8 r0 top
C37 "100nF" CAPC1005X55N#1 -43.5,54.8 r0 top
C38 "2.2UF" CAPC1608X90N 63.2,-3.7 r90 top
C39 "1.0uF" CAPC1005X55N#2 56.2,-3.3 r270 top
C40 "100uF" CAPMP3216X120N 49.2,-7.4 r180 top
C41 "100uF" CAPMP3216X120N 73.8,-6.9 r180 top
C42 "100uF" CAPMP3216X120N 70.7,-22.4 r0 top
C43 "100nF" CAPC1005X55N#1 70.3,-20.8 r180 top
C44 "100nF" CAPC1005X55N#1 50.5,-8.9 r0 top
C45 "100nF" CAPC1005X55N#1 63.4,-8.9 r180 top
C46 "100nF" CAPC1005X55N#1 68.3,-20.8 r0 top
C47 "100nF" CAPC1005X55N#1 73.8,-8.7 r0 top
C48 "10uF" CAPC1005X55N#1 -18.1,-58.7 r180 top
C49 "100nF" CAPC1005X55N#1 -18.1,-57.5 r180 top
C50 "10uF" CAPC2013X135N#1 74,-46.6 r180 top
C51 "10uF" CAPC2013X135N#1 74,-48.4 r180 top
C52 "100nF" CAPC1005X55N#1 73.44,-49.8 r180 top
C53 "100nF" CAPC1005X55N#1 73.44,-50.8 r180 top
C54 "100nF" CAPC1005X55N#1 -75,-45.8 r270 top
C55 "100nF" CAPC1005X55N#2 -76.2,-45.8 r270 top
C56 "100nF" CAPC1005X55N#1 -77.4,-45.8 r270 top
C57 "100nF" CAPC1005X55N#1 -78.6,-45.8 r270 top
C58 "100nF" CAPC1005X55N#2 -63.8,-34.9 r180 top
C59 "10uF" CAPC2013X135N#1 -60.7,-30.6 r180 top
C60 "100nF" CAPC1005X55N#1 -68.4,-41.7 r90 top
C61 "100nF" CAPC1005X55N#1 -70.9,-41.7 r90 top
C62 "10uF" CAPC2013X135N#2 -62.1,-41.7 r180 top
C63 "100nF" CAPC1005X55N#1 -76.3,-36.9 r0 top
C64 "100nF" CAPC1005X55N#1 -69.9,-29.2 r270 top
C65 "100nF" CAPC1005X55N#2 -71.5,-29.2 r270 top
C66 "10uF" CAPC2013X135N#1 -76,-27.3 r0 top
C67 "1.0uF" CAPC1005X55N#2 -76.1,-42.2 r180 top
C68 "33pF" CAPC1005X55N#1 -60.1,-37.5 r90 top
C69 "100nF" CAPC1005X55N#1 -61.1,-35.4 r180 top
C70 "10uF" CAPC2013X135N#1 -60.7,-33.9 r180 top
C71 "33pF" CAPC1005X55N#1 -63.5,-40.2 r180 top
C72 "100nF" CAPC1005X55N#2 -76.2,-32.9 r0 top
C73 "100nF" CAPC1005X55N#1 -71.9,-41.7 r90 top
C74 "100nF" CAPC1005X55N#1 -67.4,-41.7 r90 top
C75 "100nF" CAPC1005X55N#2 -63.8,-33.7 r180 top
C76 "10uF" CAPC2013X135N#1 -76.7,-31.4 r0 top
C77 "100nF" CAPC1005X55N#2 -76.2,-34.2 r0 top
C78 "100nF" CAPC1005X55N#1 -66,-28.6 r270 top
C79 "10uF" CAPC2013X135N#1 -64,-28.1 r270 top
C80 "0.22uF" CAPC1005X55N#1 -64.9,-30.7 r270 top
C81 "100nF" CAPC1005X55N#1 -53.5,-45.8 r270 top
C82 "100nF" CAPC1005X55N#2 -54.7,-45.8 r270 top
C83 "100nF" CAPC1005X55N#2 -55.9,-45.8 r270 top
C84 "100nF" CAPC1005X55N#1 -57.1,-45.8 r270 top
C85 "100nF" CAPC1005X55N#2 -44.7,-34.9 r180 top
C86 "10uF" CAPC2013X135N#2 -42.19,-30.65 r180 top
C87 "100nF" CAPC1005X55N#1 -49.4,-41.8 r90 top
C88 "100nF" CAPC1005X55N#1 -52,-41.8 r90 top
C89 "10uF" CAPC2013X135N#1 -42.6,-41.8 r180 top
C90 "100nF" CAPC1005X55N#1 -57.7,-37.1 r0 top
C91 "100nF" CAPC1005X55N#1 -56.49,-27.35 r0 top
C92 "100nF" CAPC1005X55N#1 -50.9,-29.2 r270 top
C93 "10uF" CAPC2013X135N#1 -57,-25.8 r0 top
C94 "1.0uF" CAPC1005X55N#2 -57.3,-42.4 r180 top
C95 "33pF" CAPC1005X55N#2 -40.5,-37.2 r90 top
C96 "100nF" CAPC1005X55N#1 -42.4,-35.3 r180 top
C97 "10uF" CAPC2013X135N#1 -41.8,-33.9 r180 top
C98 "33pF" CAPC1005X55N#1 -44.3,-40.2 r180 top
C99 "100nF" CAPC1005X55N#1 -57.3,-32.8 r0 top
C100 "100nF" CAPC1005X55N#1 -53,-41.8 r90 top
C101 "100nF" CAPC1005X55N#1 -48.45,-41.8 r90 top
C102 "100nF" CAPC1005X55N#2 -44.7,-33.9 r180 top
C103 "10uF" CAPC2013X135N#1 -57.4,-31.1 r0 top
C104 "100nF" CAPC1005X55N#1 -57.3,-34 r0 top
C105 "100nF" CAPC1005X55N#2 -46.9,-28.9 r270 top
C106 "10uF" CAPC2013X135N#1 -44.9,-28.4 r270 top
C107 "0.22uF" CAPC1005X55N#1 -46.1,-31.4 r270 top
C108 "100nF" CAPC1005X55N#1 15.6,-53.5 r90 top
C109 "100nF" CAPC1005X55N#2 24.6,-52.1 r90 top
C110 "100nF" CAPC1005X55N#1 64.9,53.5 r180 top
C111 "10uF" CAPC1005X55N#1 56.8,-46 r180 top
C112 "100nF" CAPC1005X55N#2 56.8,-47 r180 top
C113 "100nF" CAPC1005X55N#2 54.2,-44 r270 top
C114 "22pF" CAPC1005X55N#2 51.905,-27.3 r180 top
C115 "100nF" CAPC1005X55N#2 43.845,-46.6 r0 top
C116 "22pF" CAPC1005X55N#2 49.905,-27.3 r0 top
C117 "2.2nF" CAPC1608X90N 56.205,-36 r0 top
C118 "100nF" CAPC1005X55N#1 56.5,-50.9 r180 top
C119 "100nF" CAPC1005X55N#1 43.8,-52.2 r0 top
C120 "10uF" CAPC1005X55N#1 46.505,-40.7 r0 top
C121 "100nF" CAPC1005X55N#1 46.505,-39.7 r0 top
C122 "100nF" CAPC1005X55N#2 55.805,-40.5 r180 top
C123 "100nF" CAPC1005X55N#2 48.305,-28.8 r270 top
C124 "100nF" CAPC1005X55N#1 56.5,-51.9 r180 top
C125 "10uF" CAPC1005X55N#1 44.305,-29.9 r0 top
C126 "100nF" CAPC1005X55N#2 43.805,-33.5 r0 top
C127 "10uF" CAPC1005X55N#1 55.805,-39.4 r180 top
C128 "100nF" CAPC1005X55N#1 50.505,-41 r90 top
C129 "10uF" CAPC1005X55N#1 55.805,-38.3 r180 top
C130 "100nF" CAPC1005X55N#1 55.805,-37.3 r180 top
C131 "10uF" CAPC1005X55N#2 55.805,-34.5 r180 top
C132 "100nF" CAPC1005X55N#1 55.805,-33.5 r180 top
C133 "10uF" CAPC1005X55N#2 55.405,-28.84 r270 top
C134 "100nF" CAPC1005X55N#1 54.405,-28.8 r270 top
C135 "10uF" CAPC1005X55N#1 53.405,-28.8 r270 top
C136 "100nF" CAPC1005X55N#1 52.405,-28.8 r270 top
C137 "33pF" CAPC1005X55N#1 98.7,-35.1 r0 top
C138 "33pF" CAPC1005X55N#1 98.8,-40.1 r180 top
C139 "1.0uF" CAPC1005X55N#2 93.7,-49.5 r180 top
C140 "10uF" CAPC1005X55N#1 99,-43.9 r270 top
C141 "10uF" CAPC1005X55N#1 102.5,-43.9 r270 top
C142 "100nF" CAPC1005X55N#1 101.5,-43.9 r270 top
C143 "100nF" CAPC1005X55N#1 98,-43.9 r270 top
C144 "1.0uF" CAPC1005X55N#2 105.2,-32 r0 top
C145 "100nF" CAPC1005X55N#2 96.6,-7.1 r0 top
C146 "100nF" CAPC1005X55N#2 97.5,-25.3 r0 top
C147 "10uF" CAPC1005X55N#1 92.7,-55.7 r270 top
C148 "10uF" CAPC1005X55N#1 102.8,-41.6 r0 top
C149 "100nF" CAPC1005X55N#1 108.2,-43.1 r90 top
C150 "100nF" CAPC1005X55N#1 113.3,-39.6 r180 top
C151 "100nF" CAPC1005X55N#2 113.36,-36.8 r180 top
C152 "100nF" CAPC1005X55N#1 108.6,-32.36 r270 top
C153 "100nF" CAPC1005X55N#1 102.9,-36 r0 top
C154 "100nF" CAPC1005X55N#1 113.36,-37.8 r180 top
C155 "100nF" CAPC1005X55N#2 102.8,-38.8 r0 top
C156 "2.2UF" CAPC1608X90N 104.57,40.2 r180 top
C157 "100nF" CAPC1005X55N#2 98.6,36 r90 top
C158 "1.0uF" CAPC1005X55N#1 -70.9,35.5 r270 top
C159 "1.0uF" CAPC1005X55N#2 -69.2,38.4 r90 top
C160 "1.0uF" CAPC1005X55N#1 -70.3,38.4 r90 top
C161 "10pF" CAPC1005X55N#1 -67.1,38.4 r90 top
C162 "1.0uF" CAPC1005X55N#1 -67.1,40.7 r90 top
C163 "1.0uF" CAPC1005X55N#1 -65.9,40.7 r90 top
C164 "10pF" CAPC1005X55N#1 -61.9,40.2 r180 top
C165 "10pF" CAPC1005X55N#1 -65.9,38.4 r90 top
C166 "10pF" CAPC1005X55N#1 -64.7,38.4 r90 top
C167 "1.0uF" CAPC1005X55N#1 -64.7,40.7 r90 top
C168 "10pF" CAPC1005X55N#1 -59.7,40.2 r0 top
C169 "1.0uF" CAPC1005X55N#1 -63.5,40.7 r90 top
C170 "10pF" CAPC1005X55N#1 -63.5,38.4 r90 top
C171 "100nF" CAPC1005X55N#2 -63.8,26.2 r90 top
C172 "1.0uF" CAPC1005X55N#1 -57.5,35.4 r0 top
C173 "100nF" CAPC1005X55N#1 -70.7,28.2 r0 top
C174 "1.0uF" CAPC1005X55N#2 -58.3,38.6 r180 top
C175 "10uF" CAPC1005X55N#1 -54.3,35.4 r270 top
C176 "1.0uF" CAPC1005X55N#2 -57.5,34.1 r0 top
C177 "1.0uF" CAPC1005X55N#1 -70.7,31.5 r180 top
C178 "1.0uF" CAPC1005X55N#2 -70.7,30.4 r180 top
C179 "1.0uF" CAPC1005X55N#1 -58.3,37.4 r180 top
C180 "2.2UF" CAPC1608X90N -70.8,33.9 r0 top
C181 "1.0uF" CAPC1005X55N#1 -70.7,32.6 r0 top
C182 "10uF" CAPC1005X55N#2 -56,30.6 r90 top
C183 "1.0uF" CAPC1005X55N#1 -57.1,30.6 r270 top
C184 "1.0uF" CAPC1005X55N#2 -58.2,30.6 r270 top
C185 "100uF" CAPC3216X190N 119.7,19.1 r0 top
C186 "100nF" CAPC1005X55N#1 120.8,20.8 r0 top
C187 "100nF" CAPC1005X55N#2 83.8,-50.3 r180 top
C188 "100nF" CAPC1005X55N#2 86.2,-47.8 r180 top
C189 "1.0uF" CAPC1005X55N#2 36.8,-51.1 r0 top
C190 "CAP CER 2.2 UF 50V 10% X7R" CAPC3225X250N 34,-57.8 r270 top
C191 "100nF" CAPC1005X55N#2 16.1,-59.7 r180 top
C192 "100nF" CAPC1005X55N#2 86.3,18 r180 top
C193 "100nF" CAPC1005X55N#2 86.3,19.1 r180 top
C194 "100nF" CAPC1005X55N#2 19.4,48.7 r270 top
C195 "2.2µF" CAPC1005X55L 83,-44.1 r270 top
C196 "2.2µF" CAPC1005X55L 81.5,-43.5 r0 top
C197 "10uF" CAPC1005X55N#2 80.3,-56 r0 top
C198 "100nF" CAPC1005X55N#2 80.3,-57.1 r0 top
C199 "10uF" CAPC1005X55N#2 85.7,-53.9 r270 top
C200 "100nF" CAPC1005X55N#2 86.9,-53.9 r270 top
C201 "100nF" CAPC1005X55N#2 84.7,-51.8 r180 top
C202 "100nF" CAPC1005X55N#2 62.6,-42.2 r180 top
C203 "100nF" CAPC1005X55N#2 63.8,-45.1 r0 top
C204 "100nF" CAPC1005X55N#2 61.1,38.6 r180 top
C205 "100nF" CAPC1005X55N#2 62.2,35.8 r0 top
C206 "100nF" CAPC1005X55N#2 82.6,-8.3 r180 top
C207 "100nF" CAPC1005X55N#2 83.6,-11 r0 top
C208 "100nF" CAPC1005X55N#2 -81.5,-48.1 r180 top
C209 "100nF" CAPC1005X55N#2 -81.1,-51.1 r0 top
C210 "100nF" CAPC1005X55N#2 -58.4,-46.9 r180 top
C211 "100nF" CAPC1005X55N#2 -57.7,-49.5 r0 top
D1 "ESD9B3.3ST5G" SODFL1006X43AN12 -18,-59.7 r0 top
D2 "BAT54CWT1G" SOT65P210X100-3AN 86.8,52.9 r180 top
D3 "ESD9B3.3ST5G" SODFL1006X43AN12 7.8,50 r180 top
D4 "ESD9B3.3ST5G" SODFL1006X43AN12 5.4,50 r0 top
D5 "597-3301-507F" LEDM3020X130N_GREEN -47,51.6 r0 top
D6 "597-3401-507F" LEDM3020X130N_YELLOW -47,49.1 r0 top
D7 "ESD9B3.3ST5G" SODFL1006X43AN12 15.7,50 r180 top
D8 "ESD9B3.3ST5G" SODFL1006X43AN12 13.3,50 r0 top
D9 "ESD9B3.3ST5G" SODFL1006X43AN12 -47.7,57.5 r180 top
D10 "ESD9B3.3ST5G" SODFL1006X43AN12 -49.6,57.5 r0 top
D11 "ESD9B3.3ST5G" SODFL1006X43AN12 70.1,-50 r270 top
D12 "ESD9B3.3ST5G" SODFL1006X43AN12 71.3,-50 r270 top
D13 "ESD9B3.3ST5G" SODFL1006X43AN12 68.9,-50 r270 top
D14 "ESD9B3.3ST5G" SODFL1006X43AN12 67.7,-50 r270 top
D15 "BAT54_D87Z" SOT95P240X110_AXK-3N 40.9,-48.9 r0 top
D16 "IP4292CZ10" SON50P250X100X50-10N 90.15,-55.65 r270 top
D17 "597-3401-507F" LEDM3020X130N_YELLOW 65.8,51.025 r0 top
D18 "597-3401-507F" LEDM3020X130N_YELLOW 55.7,51.025 r0 top
D19 "ESD9B3.3ST5G" SODFL1006X43AN12 24.1,49.899 r180 top
D20 "ESD9B3.3ST5G" SODFL1006X43AN12 21.7,49.899 r0 top
D21 "1N5819HW-7-F" SOD3716X135N 85.1,-56.7 r180 top
D22 "ESDA7P60-1U1M" IND_1610 100.2,-46.7 r180 top
D23 "ESDA7P60-1U1M" IND_1610 103.7,-46.7 r180 top
D24 "ESD9B3.3ST5G" SODFL1006X43AN12 -25.8,-47.7 r90 top
D25 "ESD9B3.3ST5G" SODFL1006X43AN12 -24.5,-47.7 r90 top
D26 "ESD9B3.3ST5G" SODFL1006X43AN12 -20.6,-47.7 r90 top
D27 "ESD9B3.3ST5G" SODFL1006X43AN12 -23.2,-47.7 r90 top
D28 "ESD9B3.3ST5G" SODFL1006X43AN12 -27.1,-47.7 r90 top
D29 "ESD9B3.3ST5G" SODFL1006X43AN12 -21.9,-47.7 r90 top
D30 "ESD9B3.3ST5G" SODFL1006X43AN12 -19.3,-47.7 r90 top
D31 "597-3301-507F" LEDM3020X130N 121.2,44.6 r0 top
D32 "597-3301-507F" LEDM3020X130N 121.2,47.8 r0 top
D33 "597-3301-507F" LEDM3020X130N 121.2,51 r0 top
D34 "597-3301-507F" LEDM3020X130N 121.2,54.2 r0 top
D35 "DB2J31400L" SODFL2513X80N 83.2,14.7 r180 top
FIDUCIAL1 "40mil FID" fiducial_40mil_round -78.7,59.2 r90 top
FIDUCIAL2 "40mil FID" fiducial_40mil_round 117.3,-64.8 r90 top
FIDUCIAL3 "40mil FID" fiducial_40mil_round 117.3,59.2 r90 top
FIDUCIAL4 "40mil FID" fiducial_40mil_round -78.7,59.2 r90 bottom
FIDUCIAL5 "40mil FID" fiducial_40mil_round 117.3,-64.8 r90 bottom
FIDUCIAL6 "40mil FID" fiducial_40mil_round 117.3,59.2 r90 bottom
FIL1 "NFE31PT220R1E9L" FIL_NFE31P 107.7,43.9 r180 top
J1 "CSCD443CCS011B00G" conn_CSCD443CCS011B00G 110.8,47.496 r270 top
J2 "640456-2" TE_640456-2 101.6,59.5 r0 top
J3 "1x2" FCI_68002-102HLF#1 83.6,59.7 r0 top
J4 "1x2P" MOLEX_53047-0210_Flex 94.75,59.8 r0 top
J5 "1x2" FCI_68002-102HLF#1 83.2,51.14 r270 top
J6 "1x2" FCI_68002-102HLF#1 10.2,-42.196 r270 top
J7 "1x2" FCI_68002-102HLF#2 -28.6,-43.3 r90 top
J8 "1x2" FCI_68002-102HLF#2 -16.554,-43.4 r90 top
J9 "1x2" FCI_68002-102HLF#1 28.5,-39.9 r0 top
J10 "U.FL-R-SMT(01)" HIROSE_U.FL-R-SMT(01) -79.8,40.4 r180 top
J11 "SMA A700T" "BOBBINTRON_SMA A700T" -79.86,51.54 r180 top
J12 "FTSH-105-01-F-DV" SAMTEC_FTSH-105-01-F-DV -26.8,46.8 r270 top
J13 "USB_C" MOLEX_201267-0005 -35.4,58 r180 top
J14 "1x2" FCI_68002-102HLF#1 -10.4,54.5 r0 top
J15 "1x4P" P4_STR_C2.54_H5.84 -13,59.5 r90 top
J16 "1x2" FCI_68002-102HLF#1 0.1,54.5 r0 top
J17 "1x4P" P4_STR_C2.54_H5.84 -2.46,59.5 r90 top
J18 "1x4" MOLEX_53047-0410 -49.15,59.9 r0 top
J19 "PCIe Minicard" FOXCONN_AS0B221-S68Q-7H 62.4,-14.7 r180 top locked
J20 "FTSH-105-01-F-DV" SAMTEC_FTSH-105-01-F-DV -14.8,46.8 r270 top
J21 "FTSH-105-01-F-DV" SAMTEC_FTSH-105-01-F-DV -2.8,46.8 r270 top
J22 "78727-0001" MOLEX_78727-0001 68.4,-59.2 r270 top
J23 "500873-0806" MOLEX_500873-0806 -24.6,-62.6 r180 top
J24 "U.FL-R-SMT(01)" HIROSE_U.FL-R-SMT(01) 118.4,-35.4 r0 top
J25 "SMA A700T" "BOBBINTRON_SMA A700T" 118.34,-46.56 r0 top
J26 "RJ45" XMULTIPLE_XMG-J1B211 -75.03,-48.91 r0 top
J27 "RJ45" XMULTIPLE_XMG-J1B211 -53.56,-48.91 r0 top
J28 "1x2" FCI_68002-102HLF#1 16.14,-50 r180 top
J29 "1x40" OMRON_XF2M-4015-1A 26.1,-64.8 r0 top
J30 "SFW15S-2STE1LF" FCI_SFW15S-2STE1LF 56.9,58.375 r180 top
J31 "DF14A-20P-1.25H(25)" HIROSE_DF14A-20P-1.25H -2.7,-63.75 r180 top
J32 "HDMI21-S-RA-SMT-TR" HDMI21-S-RA-SMT-TR 48.7,-56.3 r180 top
J33 "KUSBX-AS2N" KYCON_KUSBX-AS2N_Flex 102.43,-51.77 r0 top
J34 "1x2" FCI_68002-102HLF#1 -34.5,-44.57 r90 top
J35 "SJ1-3533NG" CUI_SJ1-3533N -67.9,53 r270 top
J36 "SJ1-3533NG" CUI_SJ1-3533N -59.2,53 r270 top
J37 "SMM-110-02-F-S-P-TR" Samtec_SMM-110-02-F-S 112.3,24.275 r180 top
J38 "SMM-110-02-F-S-P-TR" Samtec_SMM-110-02-F-S 112.3,2.275 r180 top
J39 "1x8POS 0.1" J8_THT_0.1_FEMALE 112.3,-4.725 r180 top
J40 "1x8POS 0.1" J8_THT_0.1_FEMALE 112.3,-27.585 r180 top
J41 "TSW-110-26-L-D" SAMTEC_TSW-110-26-L-D -82.3,-30.5 r270 top
J42 "TSW-110-26-L-D" SAMTEC_TSW-110-26-L-D 30.9,59.2 r180 top
J43 "1x3" SAMTEC_TSW-103-07-G-S -67.06,-9 r90 top
J44 "5X2POS" MOLEX_87914-1016 -26.58,60.54 r0 top
J45 "1x3" SAMTEC_TSW-103-07-G-S -57.16,-9 r90 top
J46 "5X2POS" MOLEX_87914-1016 -81.2,35 r270 top
J47 "5X2POS" MOLEX_87914-1016 -81.2,21.8 r270 top
J48 "5X2POS" MOLEX_87914-1016 -81.2,8.3 r270 top
J49 "1x2" FCI_68002-102HLF#1 11,54.5 r0 top
J50 "1x4P" P4_STR_C2.54_H5.84 8.42,59.5 r90 top
J51 "1x3" SAMTEC_TSW-103-07-G-S -57.16,-14.8 r90 top
J52 "1x3" SAMTEC_TSW-103-07-G-S -67.06,-14.8 r90 top
J53 "1x3" SAMTEC_TSW-103-07-G-S -57.16,8.3 r90 top
J54 "1x3" SAMTEC_TSW-103-07-G-S -57.16,14.1 r90 top
J55 "1x3" SAMTEC_TSW-103-07-G-S -67.06,14.1 r90 top
J56 "1x3" SAMTEC_TSW-103-07-G-S -67.06,8.3 r90 top
J57 "1x3" SAMTEC_TSW-103-07-G-S -67.06,-3.2 r90 top
J58 "1x3" SAMTEC_TSW-103-07-G-S -67.06,2.5 r90 top
J59 "1x3" SAMTEC_TSW-103-07-G-S -57.16,-3.2 r90 top
J60 "1x3" SAMTEC_TSW-103-07-G-S -57.16,2.5 r90 top
J61 "1x3" SAMTEC_TSW-103-07-G-S -57.16,-20.6 r90 top
J62 "1x3" SAMTEC_TSW-103-07-G-S -67.06,-20.6 r90 top
J63 "USB_C" MOLEX_201267-0005 90.9,-63.5 r0 top
J64 "1x3" SAMTEC_TSW-103-07-G-S 39.84,52.3 r90 top
J65 "5X2POS" MOLEX_87914-1016 -81.2,-5.32 r270 top
J66 "1x3" SAMTEC_TSW-103-07-G-S -10.4,-43.3 r180 top
L1 "4.7uH" IND_DG6045C 84.2,34.25 r270 top
L2 "120" INDC1005X60N#1 -61.1,-28.8 r0 top
L3 "120" INDC1005X60N#2 -62.5,-43.1 r0 top
L4 "120" INDC1005X60N#2 -75.5,-25.6 r180 top
L5 "120" INDC1005X60N#2 -62.1,-32.4 r180 top
L6 "120" INDC1005X60N#2 -76.2,-29.7 r180 top
L7 "120" INDC1005X60N#2 -42.7,-29.2 r0 top
L8 "120" INDC1005X60N#1 -43,-43.6 r0 top
L9 "120" INDC1005X60N#1 -52.6,-29.2 r90 top
L10 "120" INDC1005X60N#1 -43.4,-32.2 r180 top
L11 "120" INDC1005X60N#1 -57,-29.3 r180 top
L12 "DLP11SN900" FIL_DLP11S -12.7,-58.7 r270 top
L13 "DLP11SN900" FIL_DLP11S -8.95,-58.7 r270 top
L14 "DLP11SN900" FIL_DLP11S -5.2,-58.7 r270 top
L15 "DLP11SN900" FIL_DLP11S -1.45,-58.7 r270 top
L16 "DLP11SN900" FIL_DLP11S 2.3,-58.7 r270 top
L17 "220" INDC2013X110N#1 9.5,-58.3 r270 top
L18 "DLP11SN900" FIL_DLP11S 52.7,-43.8 r270 top
L19 "DLP11SN900" FIL_DLP11S 51.2,-43.8 r270 top
L20 "DLP11SN900" FIL_DLP11S 49.7,-43.8 r270 top
L21 "DLP11SN900" FIL_DLP11S 48.2,-43.8 r270 top
L22 "220" INDC2013X110N#2 102,-46.5 r90 top
L23 "220" INDC2013X110N#2 98.5,-46.5 r90 top
L24 "220" INDC2013X110N#1 109.3,-46.7 r270 top
L25 "220" INDC2013X110N#1 111.7,-46.7 r270 top
L26 "744231121" FIL_DLW21H 84.296,-14.729 r90 top
L27 "744231121" FIL_DLW21H 90.3,-15.7 r90 top
L28 "220" INDC2013X110N#2 113.2,-33.2 r90 top
L32 "1.8K" INDC1005X60N#2 -69.2,40.7 r270 top
L33 "1.8K" INDC1005X60N#2 -70.3,40.7 r270 top
L34 "1.8K" INDC1005X60N#2 -67.1,42.6 r270 top
L35 "1.8K" INDC1005X60N#2 -65.9,42.6 r270 top
L36 "1.8K" INDC1005X60N#2 -64.7,42.6 r270 top
L37 "1.8K" INDC1005X60N#2 -63.5,42.6 r270 top
L38 "220" INDC2013X110N#2 121,16.3 r90 top
L39 "220" INDC2013X110N#2 118.9,16.3 r90 top
L42 "22uH" IND_NR4018T220M 35.9,-53.6 r180 top
LBL1 "28000351_LABEL" LABEL_10x10 11,87.7 r0 top
Q1 "ZXMN2A14FTA" SOT95P240X110_GSD-3N#1 99.2,48.4 r0 top
Q2 "NTR4003NT1G" SOT95P240X110_GSD-3N#2 121.4,41.3 r180 top
Q3 "ZXMN2A14FTA" SOT95P240X110_GSD-3N#2 43.5,-41.7 r90 top
Q4 "ZXMN2A14FTA" SOT95P240X110_GSD-3N#2 44.805,-21.9 r0 top
Q5 "ZXMN2A14FTA" SOT95P240X110_GSD-3N#2 44.805,-25.3 r0 top
Q6 "ZXMN2A14FTA" SOT95P240X110_GSD-3N#2 101.2,39.6 r180 top
Q11 "NTR4003NT1G" SOT95P240X110_GSD-3N#2 73.9,38.9 r90 top
Q12 "2N7002T" SOTFL50P160X80_GSD-3N 78.6,-49.4 r270 top
R1 "47K" RESC1005X40N 37.4,43 r270 top
R2 "0" RESC1005X40N 36.4,43 r90 top
R3 "100K" RESC1005X40N 50.3,43.5 r270 top
R4 "0" RESC1005X40N 26.6,43.1 r90 top
R5 "0" RESC1005X40N 48.1,43.5 r270 top
R6 "0" RESC1005X40N 49.2,43.5 r270 top
R7 "10.0K" RESC1005X40N 96.2,50.9 r180 top
R8 "100K" RESC1005X40N 93.5,49 r90 top
R9 "0" RESC1005X40N 93.5,44.4 r180 top
R10 "10.0K" RESC1005X40N 100.5,44.8 r270 top
R11 "0" RESC1005X40N 121.3,35.6 r0 top
R12 "220" RESC1005X40N 118.3,44.5 r270 top
R13 "0" RESC1005X40N 103.8,47.7 r90 top
R14 "100K" RESC1005X40N 101.4,47.7 r270 top
R15 "220" RESC1005X40N 118.3,47.78 r270 top
R16 "0" RESC1609X55N#1 84.9,57.1 r180 top
R17 "0" RESC1609X55N#1 93.9,57.6 r180 top
R18 "0" RESC1005X40N 83.3,54.8 r90 top
R19 "12K" RESC1609X55N#1 89.3,53 r270 top
R20 "2.2K" RESC1005X40N 90.8,50.8 r0 top
R21 "20K" RESC1609X55N#1 90.1,55.4 r180 top
R22 "2.2M" RESC0603X28N 90.3,49.6 r270 top
R23 "0" RESC1609X55N#1 78.7,37.3 r270 top
R24 "0" RESC1609X55N#1 87.7,28.8 r180 top
R25 "100K" RESC1005X40N 76.8,39 r180 top
R26 "0" RESC1005X40N 76.8,40 r0 top
R27 "470K" RESC1005X40N 85.5,42.7 r0 top
R28 "53.6k" RESC1609X55N#1 79.4,42.4 r180 top
R29 "100K" RESC1005X40N 95.9,30.5 r90 top
R30 "100K" RESC1005X40N 83,43.2 r270 top
R31 "470K" RESC1005X40N 84.1,43.2 r270 top
R32 "12K" RESC1609X55N#1 79.4,43.8 r0 top
R33 "0" RESC1609X55N#1 12.4,-43.3 r270 top
R34 "0" RESC1609X55N#1 8,-43.3 r90 top
R35 "0" RESC1609X55N#2 6.4,-43.265 r90 top
R36 "0" RESC1005X40N 44.8,-4.3 r270 top
R37 "0" RESC1005X40N 14.4,-37.3 r0 top
R38 "0" RESC1609X55N#1 -9.1,-37.4 r180 top
R39 "0" RESC1005X40N -6.1,-36.9 r90 top
R40 "0" RESC1005X40N -5.1,-36.9 r90 top
R41 "0" RESC1005X40N -44.5,-0.58 r270 top
R42 "0" RESC1005X40N 44.5,10.42 r270 top
R43 "0" RESC1609X55N#2 -31.2,-43.3 r270 top
R44 "0" RESC1609X55N#2 -13.654,-43.3 r270 top
R45 "0" RESC1005X40N -13.7,-37.3 r180 top
R46 "0" RESC1005X40N 67.2,19.7 r90 top
R47 "0" RESC1005X40N 67.2,17.6 r270 top
R48 "0" RESC1005X40N 68.2,19.7 r90 top
R49 "0" RESC1005X40N 68.2,17.6 r270 top
R50 "10.0K" RESC1005X40N 109.3,-30.2 r180 top
R51 "10.0K" RESC1005X40N 80.8,-50.2 r0 top
R52 "0" RESC1005X40N -44.8,-7.4 r180 top
R53 "0" RESC1005X40N -44.8,-8.4 r180 top
R54 "0" RESC1005X40N -44.8,-9.4 r180 top
R55 "0" RESC1005X40N -44.8,-10.4 r180 top
R56 "0" RESC1005X40N -44.8,-11.4 r180 top
R57 "0" RESC1005X40N -44.8,-12.4 r180 top
R58 "0" RESC1005X40N -79.8,44.8 r270 top
R59 "0" RESC1005X40N -79.3,43.3 r180 top
R60 "0" RESC1005X40N -79.3,46.3 r180 top
R61 "0" RESC1005X40N -44.8,-3.4 r180 top
R62 "0" RESC1005X40N -44.8,-4.4 r180 top
R63 "0" RESC1005X40N -44.8,-5.4 r180 top
R64 "0" RESC1005X40N -44.8,-6.4 r180 top
R65 "0" RESC1005X40N 10,48.7 r90 top
R66 "120" RESC1005X40N -4.9,54.5 r180 top
R67 "1.0K" RESC1005X40N 3.1,48.7 r270 top
R68 "0" RESC1005X40N -46.4,56.1 r0 top
R69 "0" RESC1005X40N -46.4,54.9 r0 top
R70 "120" RESC1005X40N -49.7,51.52 r90 top
R71 "120" RESC1005X40N -49.7,49.02 r90 top
R72 "10.0K" RESC1005X40N -41.3,47.2 r270 top
R73 "0" RESC1609X55N#1 -46.3,40.8 r180 top
R74 "0" RESC1609X55N#1 -46.3,42.3 r180 top
R75 "0" RESC1005X40N 17.9,48.7 r90 top
R76 "12K" RESC1609X55N#1 -42.7,43 r270 top
R77 "120" RESC1005X40N 5.6,54.5 r180 top
R78 "1.0K" RESC1005X40N 11.1,48.7 r270 top
R79 "20K" RESC1609X55N#1 -43.4,45.2 r0 top
R80 "10.0K" RESC1005X40N 51.1,-20.7 r0 top
R81 "0" RESC1005X40N 64.6,-6.8 r270 top
R82 "100K" RESC1005X40N 61.8,-3.3 r90 top
R83 "20K" RESC1609X55N#2 59.5,-6.2 r0 top
R84 "0" RESC1005X40N -18.1,-53.9 r0 top
R85 "0" RESC1005X40N -18.1,-55.1 r0 top
R86 "22" RESC1005X40N 57.6,-22 r270 top
R87 "0" RESC1005X40N -18.1,-52.7 r0 top
R88 "0" RESC1005X40N -18.1,-56.3 r0 top
R89 "22" RESC1005X40N 56.6,-22 r270 top
R90 "10.0K" RESC1005X40N -27.1,-49.6 r270 top
R91 "100K" RESC1005X40N -25.8,-49.6 r90 top
R92 "10.0K" RESC1005X40N -24.5,-49.6 r270 top
R93 "22" RESC1005X40N -19.3,-49.5 r270 top
R94 "0" RESC1005X40N 118.4,-40 r270 top
R95 "0" RESC1005X40N 118.9,-38.5 r180 top
R96 "0" RESC1005X40N 118.9,-41.5 r180 top
R97 "120" RESC1005X40N -82.6,-53.2 r270 top
R98 "120" RESC1005X40N -81.6,-53.2 r270 top
R99 "4.99K" RESC1005X40N -78.5,-35.7 r90 top
R100 "0" RESC3225X60N -37,-50.7 r270 top
R101 "0" RESC1609X55N#1 -76.5,-39.8 r0 top
R102 "0" RESC1609X55N#1 -76.5,-38.3 r0 top
R103 "10.0K" RESC1005X40N -76.1,-41.1 r180 top
R104 "0" RESC1005X40N -22.5,-37.7 r90 top
R105 "0" RESC1609X55N#1 -66,-24.2 r270 top
R106 "4.99K" RESC1005X40N -65.5,-40.6 r90 top
R107 "120" RESC1005X40N -59.2,-51.7 r270 top
R108 "120" RESC1005X40N -58.1,-51.7 r270 top
R109 "4.99K" RESC1005X40N -58.4,-35.5 r0 top
R110 "0" RESC1609X55N#1 -57.7,-40 r0 top
R111 "0" RESC1609X55N#1 -57.7,-38.4 r0 top
R112 "10.0K" RESC1005X40N -57.3,-41.4 r180 top
R113 "0" RESC1005X40N -23.5,-37.7 r90 top
R114 "4.99K" RESC1005X40N -46.4,-40.4 r90 top
R115 "10.0K" RESC1005X40N 14.5,-56 r90 top
R116 "0" RESC1609X55N#2 13.7,-53.2 r90 top
R117 "10.0K" RESC1005X40N 13.5,-56 r270 top
R118 "10.0K" RESC1005X40N 7.8,-58.7 r270 top
R119 "0" RESC1005X40N 55.2,-44 r90 top
R120 "27K" RESC1005X40N 43.8,-48.9 r0 top
R121 "0" RESC1005X40N 44.705,-38 r90 top
R122 "10.0K" RESC1005X40N 45.9,-28.3 r270 top
R123 "1M_1%" RESC1005X40N 50.905,-28.4 r0 top
R124 "5.97K" RESC1005X40N 43.605,-38 r270 top
R125 "0" RESC1005X40N 49.505,-28.8 r270 top
R126 "15.0k" RESC1005X40N 43.8,-53.3 r0 top
R127 "47K" RESC1005X40N 43.8,-45.4 r0 top
R128 "4.7K" RESC1005X40N 43.8,-50 r0 top
R129 "4.7K" RESC1005X40N 43.8,-51.1 r0 top
R130 "1.0K" RESC1005X40N 43.8,-44.2 r180 top
R131 "2.2K" RESC1005X40N 42.2,-39.4 r180 top
R132 "0" RESC1005X40N 44.2,-39.4 r180 top
R133 "1.0K" RESC1005X40N 42.2,-21.9 r90 top
R134 "2.2K" RESC1005X40N 47.9,-20.8 r0 top
R135 "0" RESC1005X40N 47.405,-22.4 r90 top
R136 "1.0K" RESC1005X40N 42.2,-25.3 r90 top
R137 "2.2K" RESC1005X40N 47.305,-24.9 r90 top
R138 "0" RESC1005X40N 44.8,-28.3 r90 top
R139 "10.0K" RESC1005X40N 94.3,-40.3 r90 top
R140 "10.0K" RESC1005X40N 93.1,-40.3 r90 top
R141 "0" RESC1609X55N#1 95.1,-31.9 r0 top
R142 "1M_1%" RESC1005X40N 100.9,-38 r270 top
R143 "10.0K" RESC1005X40N 105.18,-33 r180 top
R144 "47K" RESC1005X40N 102.88,-35 r180 top
R145 "12K" RESC1609X55N#1 102.3,-40.2 r0 top
R146 "47K" RESC1005X40N 109.6,-32.4 r270 top
R147 "47K" RESC1005X40N 107.6,-32.4 r270 top
R148 "47K" RESC1005X40N 106.6,-32.4 r270 top
R149 "47K" RESC1005X40N 80.8,-52.2 r0 top
R150 "52.3k" RESC1005X40N 80.3,-54.9 r0 top
R151 "10.0K" RESC1005X40N 97.3,36 r90 top
R152 "316K" RESC1609X55N#1 104.6,38.6 r180 top
R153 "4.7K" RESC1005X40N 121.28,38.1 r0 top
R154 "220" RESC1005X40N 118.3,50.9 r270 top
R155 "4.7K" RESC1005X40N 121.28,33.1 r0 top
R156 "4.7K" RESC1005X40N 121.3,30.5 r0 top
R157 "100K" RESC1005X40N 102.8,27.9 r90 top
R158 "100K" RESC1005X40N 101.3,27.9 r90 top
R159 "100K" RESC1005X40N 99.8,27.9 r90 top
R160 "10.0K" RESC1005X40N -68.6,26.3 r90 top
R161 "0" RESC1005X40N -66.5,26.3 r90 top
R162 "0" RESC1005X40N -65.5,26.3 r90 top
R163 "0" RESC1005X40N -70.7,29.3 r0 top
R164 "0" RESC1005X40N -67.5,26.3 r90 top
R165 "2.2K" RESC1005X40N -69.8,35.5 r90 top
R166 "0" RESC1005X40N -69.2,42.6 r90 top
R167 "0" RESC1005X40N -70.3,42.6 r90 top
R168 "0" RESC1005X40N -61.4,41.6 r90 top
R169 "0" RESC1005X40N -60.2,41.6 r90 top
R170 "0" RESC1609X55N#1 -54.9,25.7 r90 top
R171 "0" RESC1609X55N#1 -52.1,34.9 r180 top
R172 "1.0K" RESC1005X40N 65.8,24.8 r270 top
R173 "2.2K" RESC1005X40N 59.9,27.6 r90 top
R174 "1.0K" RESC1005X40N 65.8,27.6 r90 top
R175 "2.2K" RESC1005X40N 59.9,25.7 r270 top
R176 "0" RESC1005X40N 61.1,26.6 r90 top
R177 "0" RESC1005X40N 64.3,26.6 r270 top
R178 "0" RESC1005X40N 65.2,19.7 r90 top
R179 "0" RESC1005X40N 69.2,24.8 r270 top
R180 "2.2K" RESC1005X40N 63.1,19.7 r90 top
R181 "2.2K" RESC1005X40N 63.1,17.6 r270 top
R182 "0" RESC1005X40N 65.2,17.6 r270 top
R183 "0" RESC1005X40N 69.2,27.6 r90 top
R184 "0" RESC1005X40N 64.2,19.7 r90 top
R185 "0" RESC1005X40N 67,24.8 r270 top
R186 "0" RESC1005X40N 64.2,17.6 r270 top
R187 "0" RESC1005X40N 67,27.6 r90 top
R188 "0" RESC1005X40N 66.2,19.7 r90 top
R189 "0" RESC1005X40N 68.1,24.8 r270 top
R190 "0" RESC1005X40N 66.2,17.6 r270 top
R191 "0" RESC1005X40N 68.1,27.6 r90 top
R192 "10.0K" RESC1005X40N 80.8,-51.2 r0 top
R193 "100K" RESC1005X40N 81.5,-44.6 r180 top
R194 "0" RESC1005X40N 115.2,20.1 r90 top
R195 "220" RESC1005X40N 118.3,54.1 r270 top
R196 "0" RESC1005X40N 111.3,20.1 r90 top
R197 "0" RESC1005X40N 109.3,6.6 r90 top
R198 "10.0K" RESC1005X40N 113.8,6.1 r180 top
R199 "1.0K" RESC1005X40N 80.3,-53.9 r0 top
R200 "0" RESC1005X40N 103.8,-1.6 r0 top
R201 "22.1K" RESC1005X40N 78.6,-53.4 r270 top
R202 "100K" RESC1005X40N 78.6,-47.4 r0 top
R203 "100K" RESC1005X40N 118.7,41.3 r270 top
R204 "100K" RESC1005X40N 117.6,41.3 r90 top
R205 "0" RESC1609X55N#1 -37.2,-43.3 r90 top
R206 "120" RESC1005X40N 65,49 r0 top
R207 "120" RESC1005X40N 54.9,49 r0 top
R208 "120" RESC1005X40N 62.2,43.62 r270 top
R209 "120" RESC1005X40N 51.5,43.5 r270 top
R210 "10.0K" RESC1005X40N 61.7,-45.1 r0 top
R211 "10.0K" RESC1005X40N 60.2,35.8 r0 top
R212 "0" RESC1005X40N 35.9,-61.3 r0 top
R213 "0" RESC1005X40N 34.4,-60.9 r90 top
R214 "10.0K" RESC1005X40N 12.7,-60.2 r270 top
R215 "10.0K" RESC1005X40N 37.9,-60.1 r90 top
R216 "0" RESC1005X40N 37.3,-49.7 r270 top
R217 "10.0" RESC1005X40N 36.6,-59.7 r180 top
R218 "10.0K" RESC1005X40N 13.6,-60.2 r90 top
R219 "0" RESC1005X40N 16.1,-60.6 r180 top
R220 "0" RESC1005X40N 29.7,-60.9 r90 top
R221 "0" RESC1005X40N 28.8,-60.9 r90 top
R222 "0" RESC1005X40N 27.9,-60.9 r90 top
R223 "0" RESC1005X40N 27,-60.9 r90 top
R224 "10.0K" RESC1005X40N 79.9,20.2 r180 top
R225 "10.0K" RESC1005X40N 79.9,19.1 r180 top
R226 "0" RESC1005X40N 86.3,16.9 r0 top
R227 "0" RESC1005X40N 86.3,15.8 r0 top
R228 "0" RESC1005X40N 79.9,18 r0 top
R229 "10.0K" RESC1005X40N 86.3,20.2 r180 top
R230 "0" RESC1005X40N 69.2,19.7 r90 top
R231 "0" RESC1005X40N 69.2,17.6 r270 top
R232 "10.0K" RESC1005X40N 20.9,40.7 r270 top
R233 "0" RESC1005X40N 22.2,40.7 r90 top
R234 "0" RESC1005X40N 23.5,40.7 r90 top
R235 "0" RESC1005X40N 24.8,40.7 r90 top
R236 "120" RESC1005X40N 16.5,54.5 r180 top
R237 "10.0K" RESC1005X40N 81.6,-11 r0 top
R238 "10.0K" RESC1005X40N -83.4,-51.1 r0 top
R239 "10.0K" RESC1005X40N -59.8,-49.5 r0 top
R240 "0" RESC1005X40N -16.5,-37.7 r90 top
R241 "0" RESC1005X40N -15.5,-37.7 r90 top
R242 "100" RESC1005X40N 86.3,14.7 r180 top
R243 "0" RESC1005X40N 69.7,-6.8 r270 top
R244 "0" RESC1005X40N 43.8,-47.8 r180 top
SW1 "KSC221JLFS" SW_KSC221J 31.4,43.727 r90 top
SW2 "KSC221JLFS" SW_KSC221J 43.3,43.727 r270 top
SW3 "219-4LPSTR" SOIC254P991X420-8N 114.3,34.3 r0 top
SW4 "KSC221JLFS" SW_KSC221J 67,43.5 r90 top
SW5 "KSC221JLFS" SW_KSC221J 56.481,43.5 r90 top
SWD "TC2050-IDC-NL" TC_TC2050-IDC-NL -3.1,39.7 r0 top
TP1 "TESTPOINT" TP0762 44.8,0.1 r90 top
TP2 "TESTPOINT" TP0762 44.8,-1.2 r0 top
TP3 "TESTPOINT" TP0762 44.8,1.4 r90 top
TP4 "TESTPOINT" TP0762 44.8,4.1 r180 top
TP5 "TESTPOINT" TP0762 44.8,2.7 r180 top
TP6 "TESTPOINT" TP0762 44.8,5.6 r180 top
TP7 "TESTPOINT" TP0762 -77.5,-36.2 r0 top
TP8 "TESTPOINT" TP0762 -76.7,-28.7 r180 top
TP9 "TESTPOINT" TP0762 -66,-30 r180 top
TP10 "TESTPOINT" TP0762 -58.9,-36.4 r0 top
TP11 "TESTPOINT" TP0762 -57.5,-28.3 r180 top
TP12 "TESTPOINT" TP0762 -46.9,-30.3 r90 top
TP13 "TESTPOINT" TP0762 -62.5,26.2 r90 top
TP14 "TESTPOINT" TP0762 -60.3,26.2 r90 top
TP15 "TESTPOINT" TP0762 -58.1,26.2 r90 top
TP16 "TESTPOINT" TP0762 -59.2,26.2 r90 top
TP17 "TESTPOINT" TP0762 -61.4,26.2 r90 top
TP18 "TESTPOINT" TP0762 81.4,20.6 r90 top
TP19 "TESTPOINT" TP0762 -45.4,-22.2 r90 top
TP20 "TESTPOINT" TP0762 -45.4,-20.4 r90 top
U1 "STEF4SPUR" SON50P300X300X80-11T164X238N 96.8,43.7 r180 top
U2 "SI2323DS-T1-E3" SOT95P240X110_GSD-3N#2 95.8,48.4 r270 top
U3 "AP2202" SOT95P280X145-5N 92.3,53 r180 top
U4 "MCP6442T-E/MNY" SON50P300X200X80-9N 87.1,50.1 r90 top
U5 "SIP32401A" SON50P120X160X60-5T55X91N 95.1,28.5 r0 top
U6 "MP2316" QFN_MPS_MP2316 82,40.1 r180 top
U7 "CCIMX93" CC93_DVK 0,0 r0 top locked
U8 "TCAN1042HGVDR" SOIC127P600X175-8N#1 6.6,45.7 r90 top
U9 "CY7C65211-24LTXI" QFN50P400X400X100-25 -41,50.85 r0 top
U10 "TCAN1042HGVDR" SOIC127P600X175-8N#2 14.5,45.7 r90 top
U11 "AP2202" SOT95P280X145-5N -39.7,43.1 r180 top
U12 "AP2202" SOT95P280X145-5N 59,-3.8 r0 top
U13 "88E1512-A0-NNP2C000" QFN56P8mmx8mm-4.50mmPAD -70.15,-35.2 r0 top
U14 "88E1512-A0-NNP2C000" QFN56P8mmx8mm-4.50mmPAD -51.2,-35.2 r0 top
U15 "NX3DV642" QFN40P340X250X50-24N 18.8,-53.5 r270 top
U16 "NX3DV642" QFN40P340X250X50-24N 27.9,-52.1 r270 top
U17 "LT8912B" QFN40P750X750X80-65T620N 49.7,-34.7 r0 top
U18 "CM2020-01" SOP50P640X120-38N 50.2,-49.4 r270 top
U19 "MIC2026" SOIC127P600X175-8N#1 93.7,-45.1 r270 top
U20 "USB2514BI-AEZG" QFN50P600X600X100-37AN 107.9,-37.6 r90 top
